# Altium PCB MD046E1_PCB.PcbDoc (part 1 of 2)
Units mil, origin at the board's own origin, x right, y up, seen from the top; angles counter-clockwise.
Board outline 4143.7 x 2795.28 mil, 4 copper layers (Top Layer, Signal Layer 1, Signal Layer 2, Bottom Layer), stack 62.8 mil thick; 159 components, 76 nets, 432 pads, 579 vias.
Unrouted connection lines stored in the file: 13.
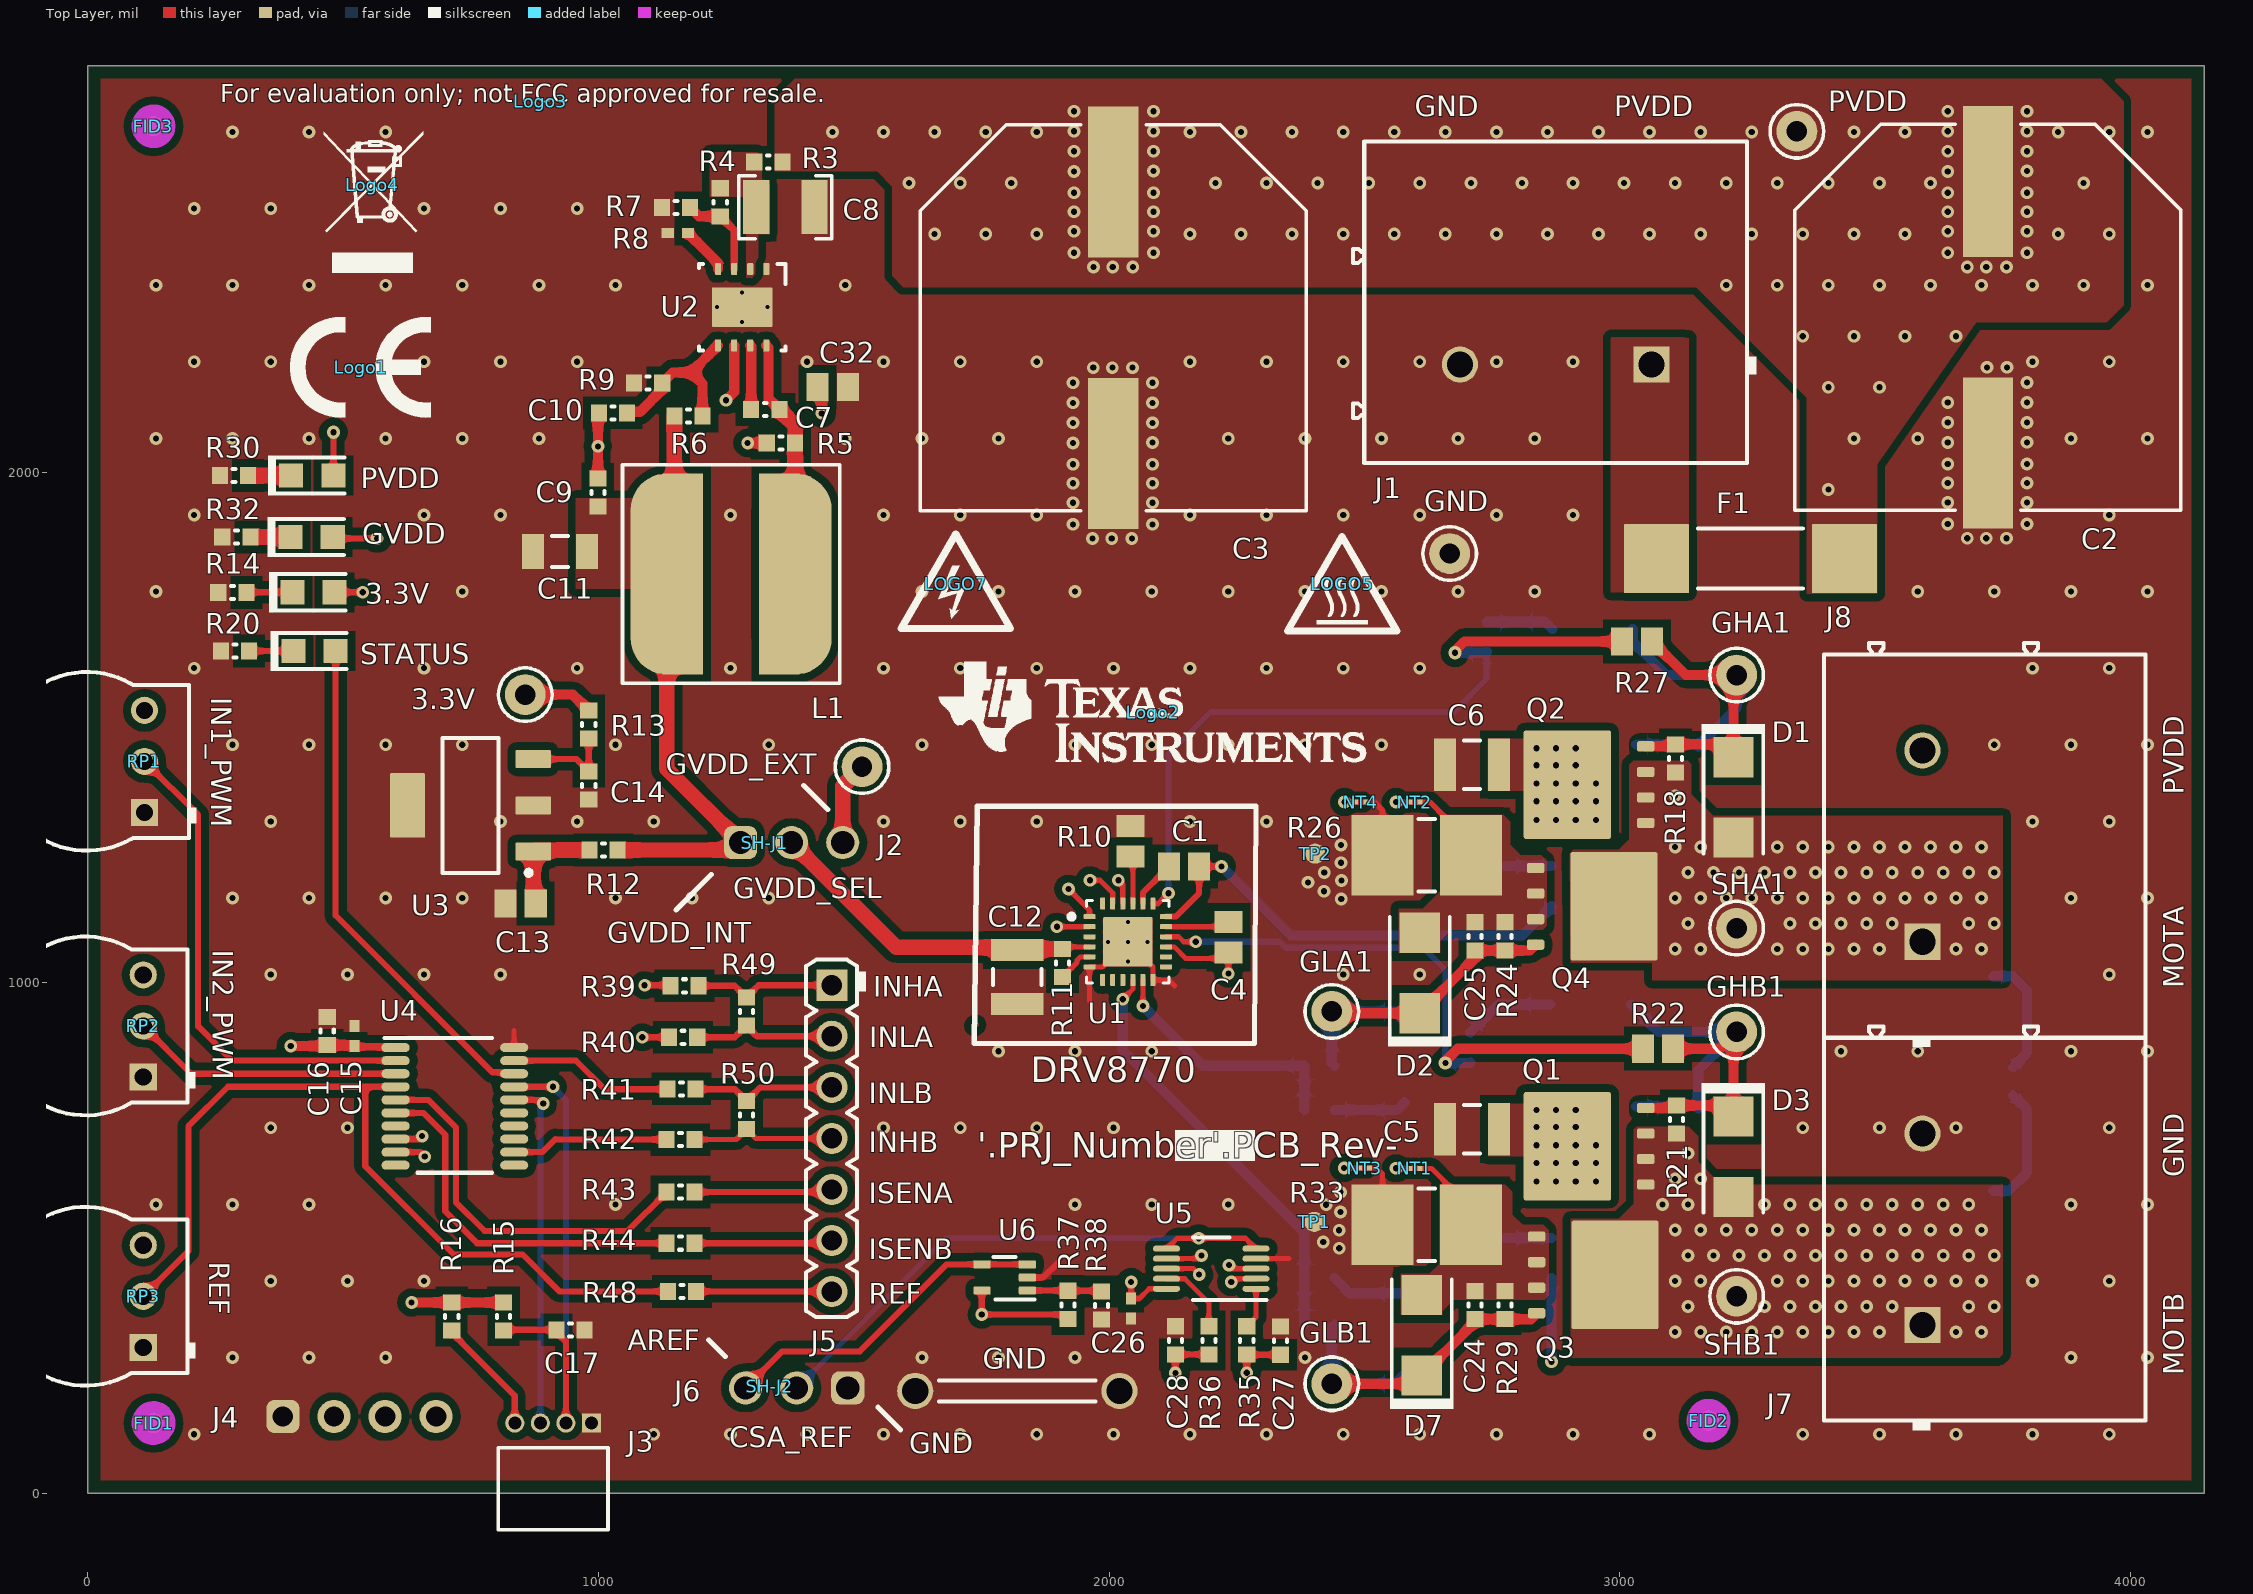
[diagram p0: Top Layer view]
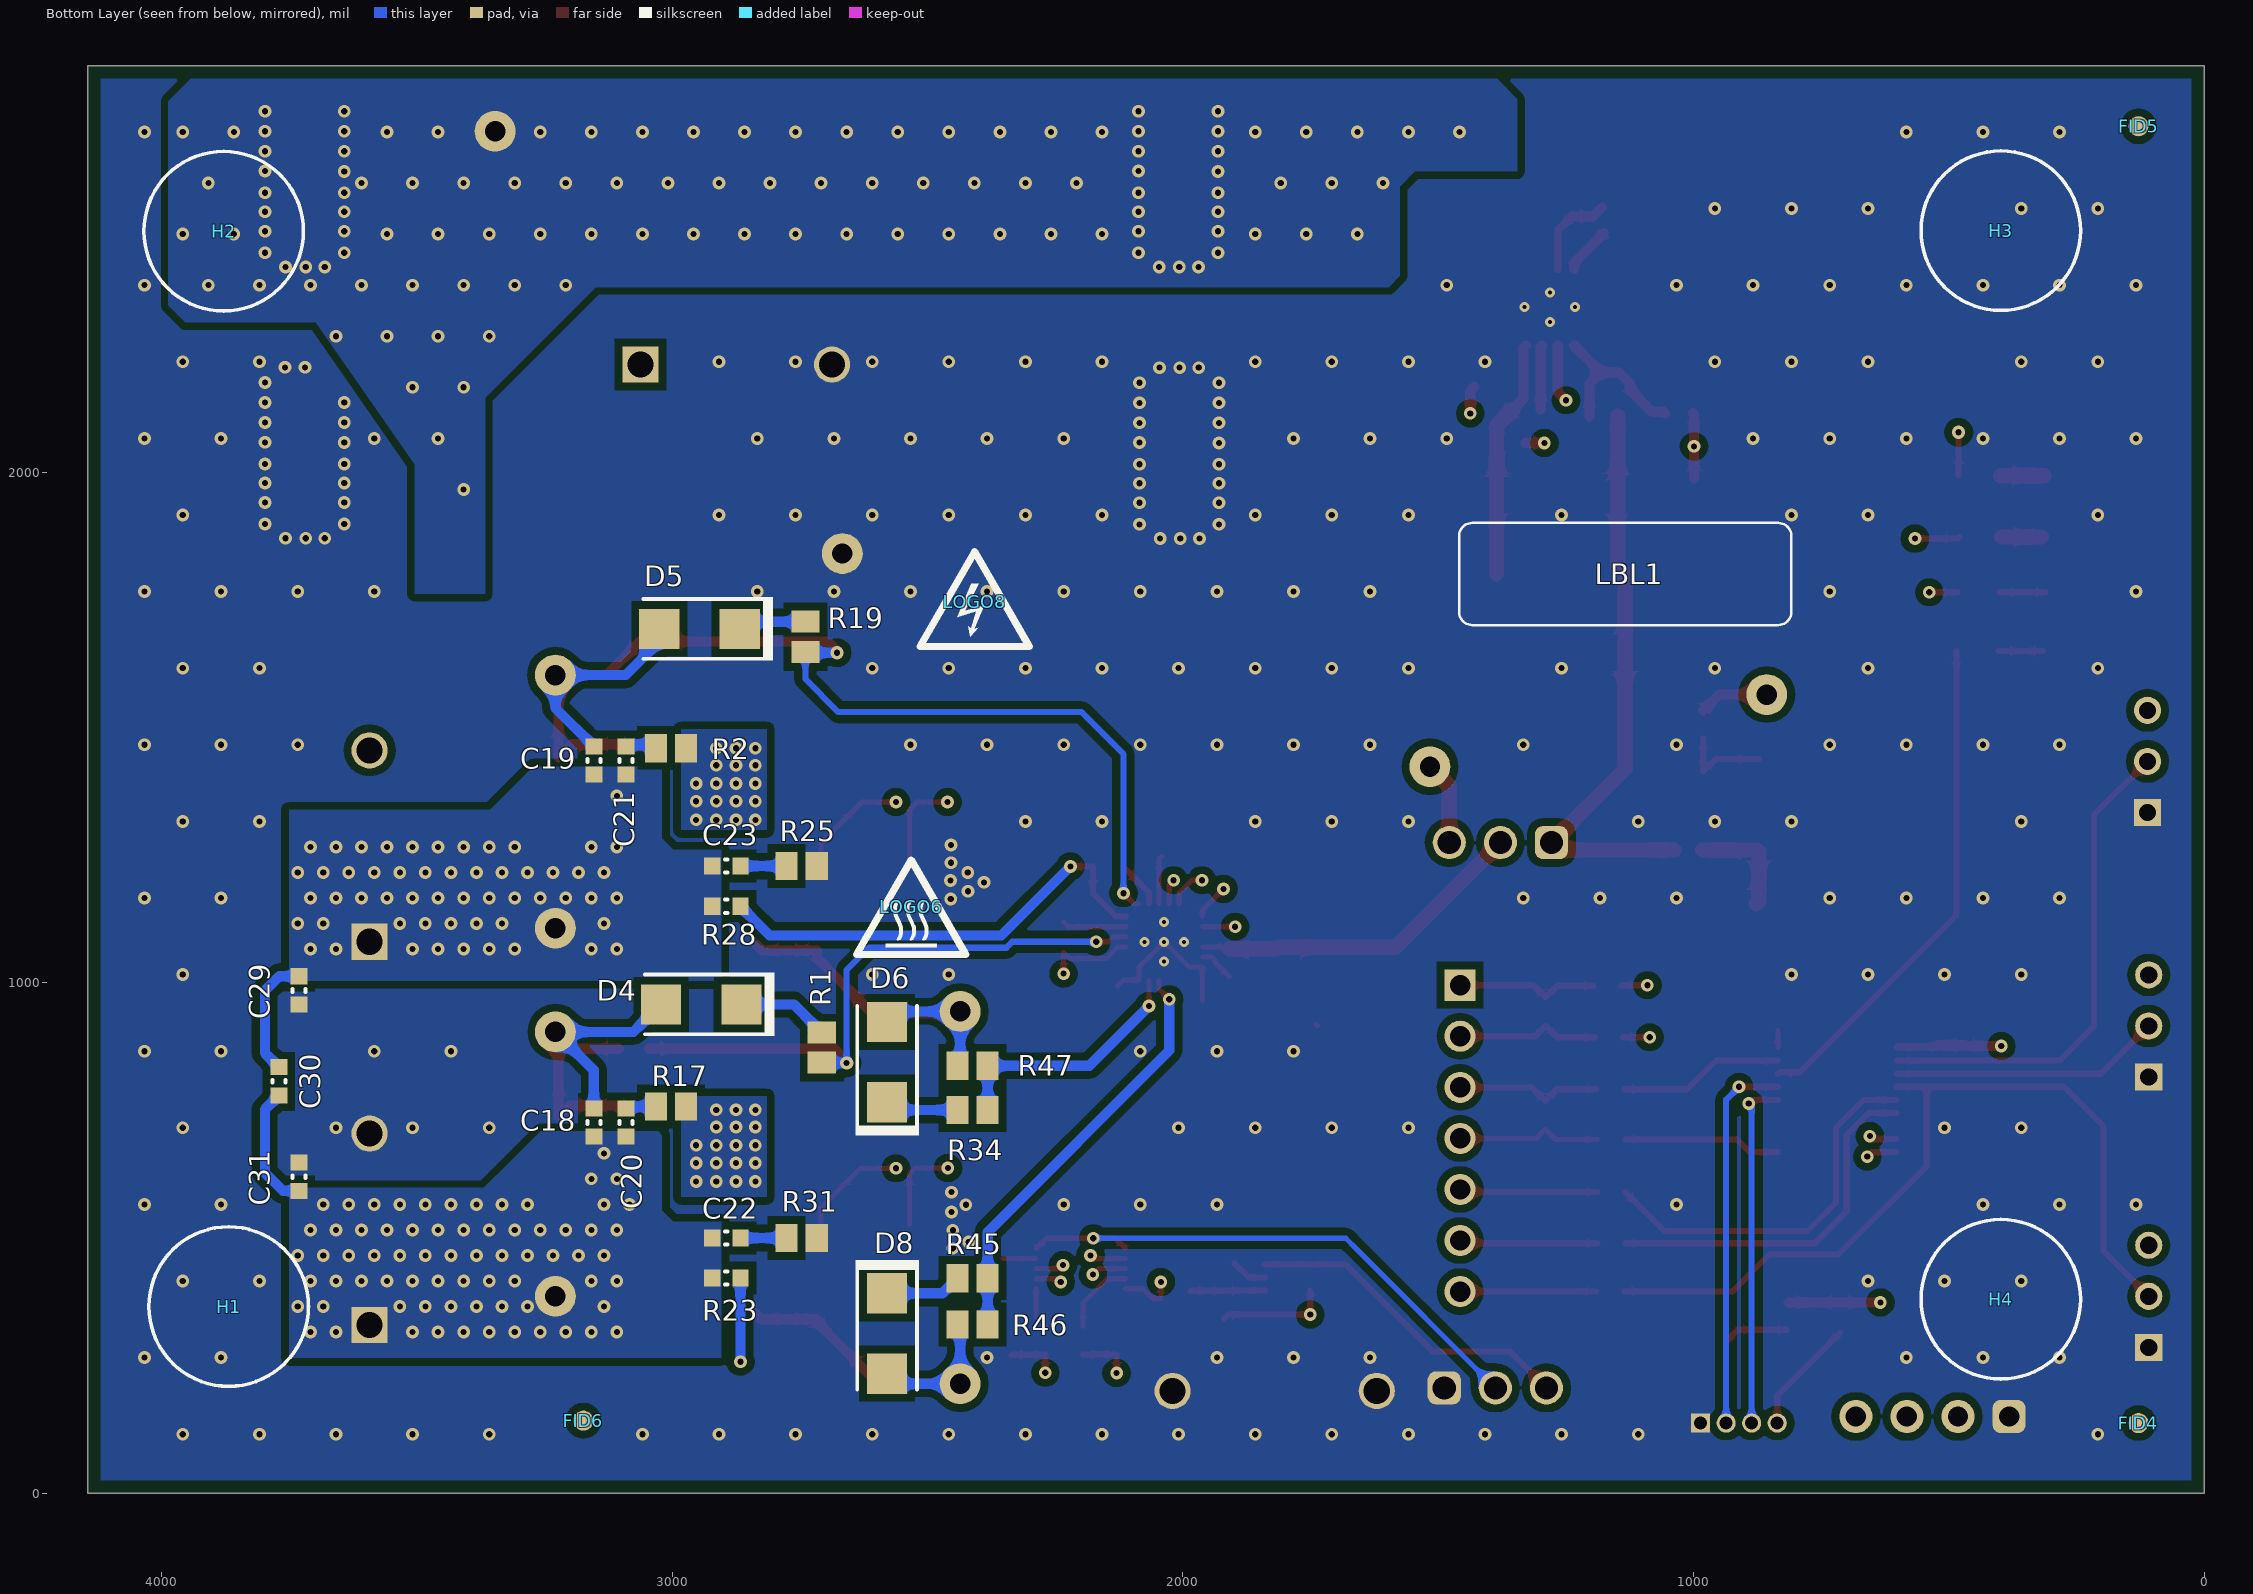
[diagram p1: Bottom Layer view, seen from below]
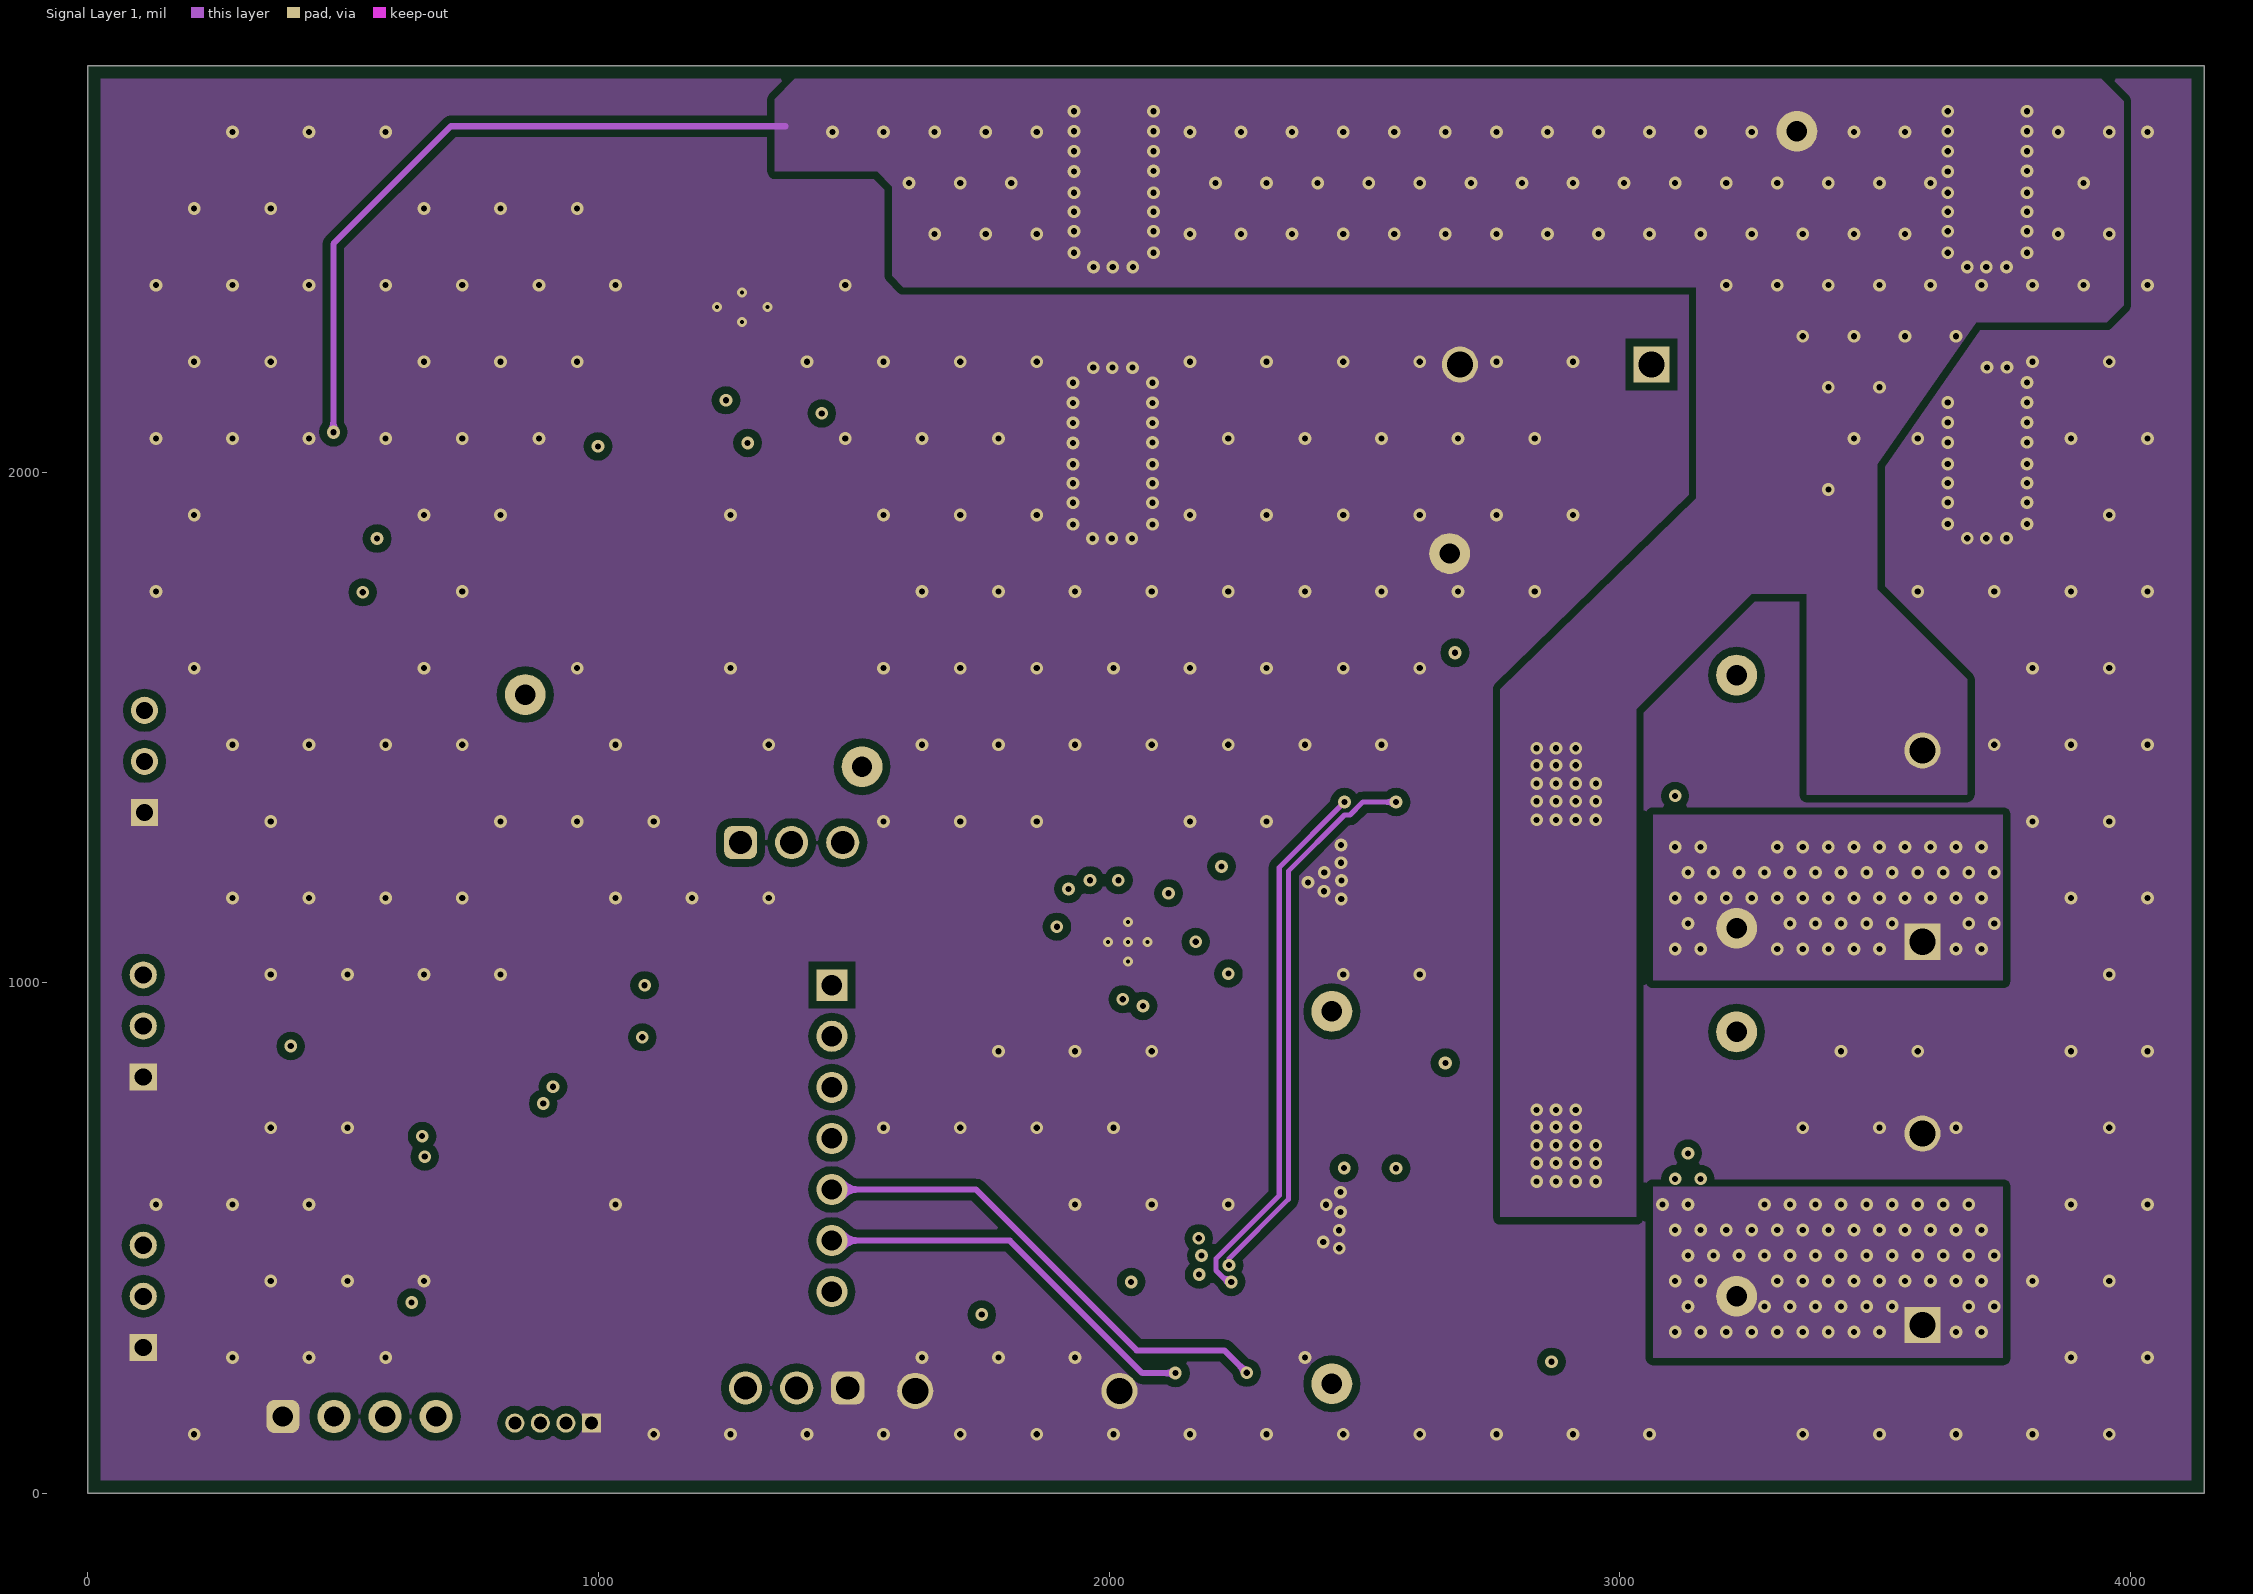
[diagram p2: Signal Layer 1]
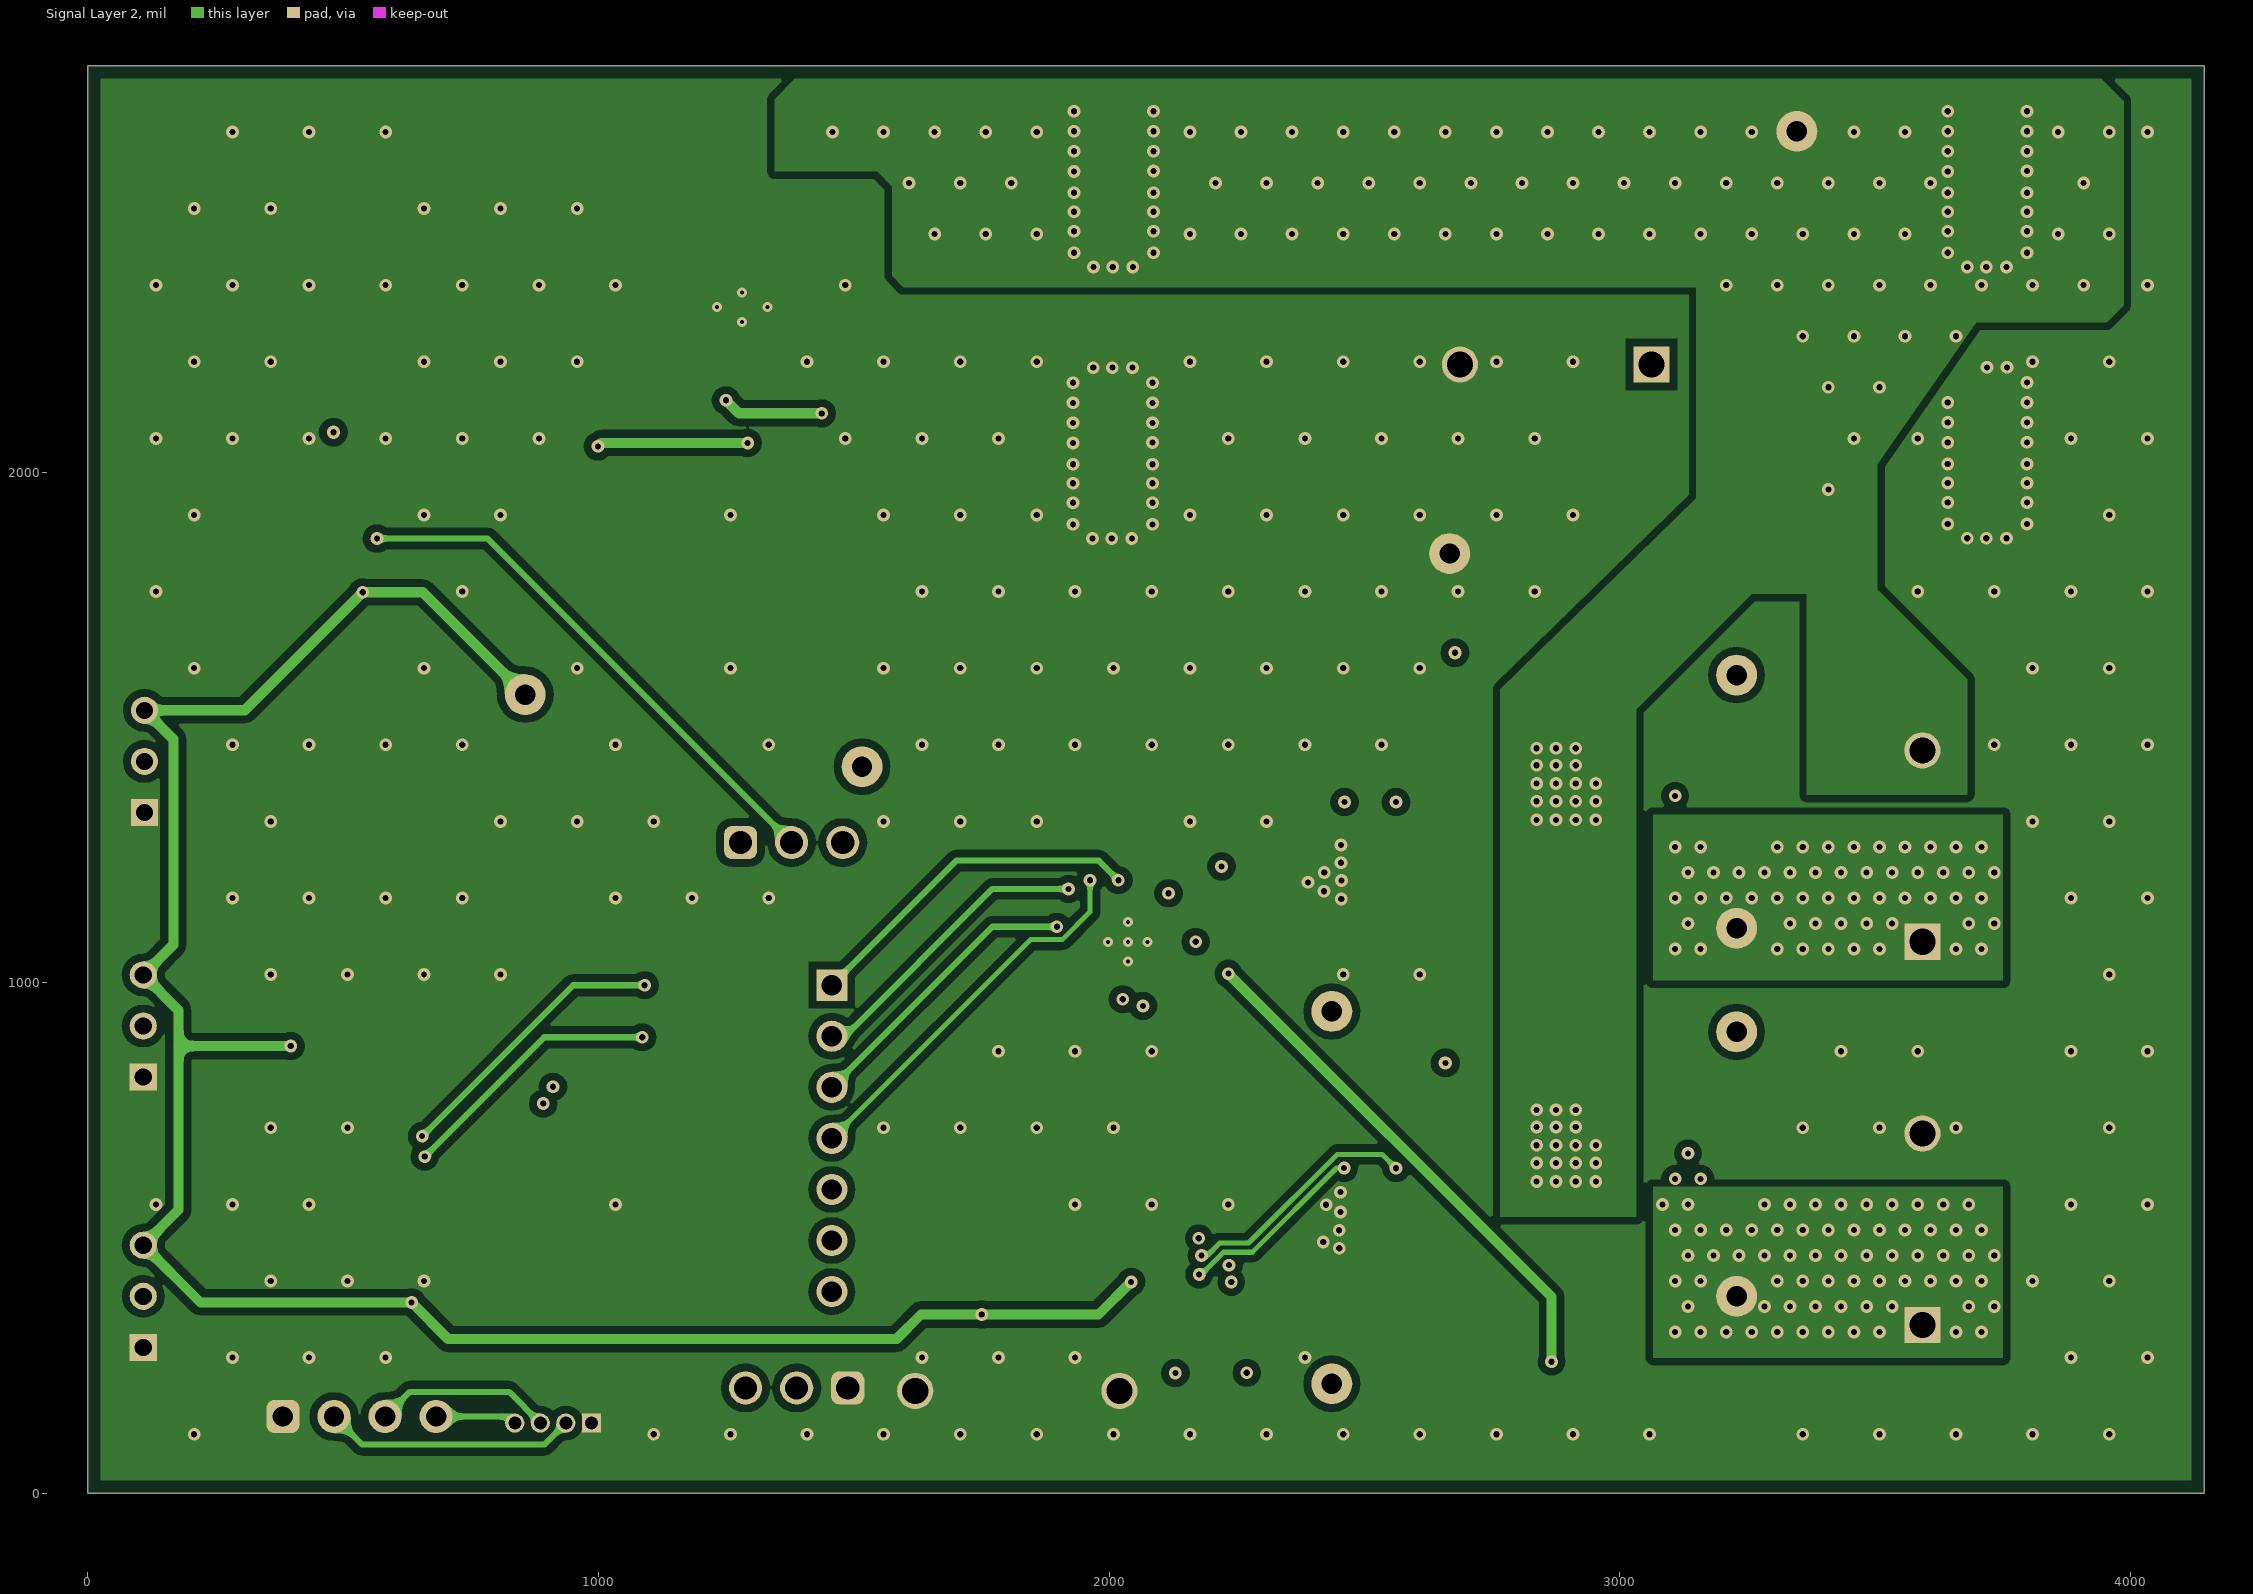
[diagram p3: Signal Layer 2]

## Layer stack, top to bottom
Top Solder: solder mask 0.4, Solder Resist, Dk 3.5
Top Layer: signal copper 2.8
Dielectric 1: prepreg 8, FR-4, Dk 4.2
Signal Layer 1: signal copper 1.4
Dielectric 2: core 38.4, FR-4, Dk 4.2
Signal Layer 2: signal copper 1.4
Dielectric 3: prepreg 8, FR-4, Dk 4.2
Bottom Layer: signal copper 2.8
Bottom Solder: solder mask 0.4, Solder Resist, Dk 3.5

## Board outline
0,0 4143.7,0 4143.7,2795.28 0,2795.28
cut-out: -692,-1534 -682,-1534 -682,-1524 -692,-1524

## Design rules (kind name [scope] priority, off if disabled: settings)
AcuteAngle [All] p1: minimum=4.50000000000000E+0001 checktracksonly=FALSE
AssemblyTestPointUsage [All] p1: valid=2
BoardOutlineClearance BoardOutlineClearance_MountingHoles [OnCopper and InComponentClass('Mounting Holes')] p1: gap=39.37 ignorepadtopadclearanceinfootprint=FALSE
BoardOutlineClearance BoardOutlineClearance_Poly [OnCopper and IsPoly] p2: gap=25 ignorepadtopadclearanceinfootprint=FALSE
BoardOutlineClearance [OnCopper and Not InComponentClass('Logo') and not InComponentClass('FiducialMark') and not InRegion(1000,500,4000,800) and not InPoly] p3: gap=75 ignorepadtopadclearanceinfootprint=FALSE
Clearance Clearance_Keepouts [((IsTrack Or IsArc) And Not InPoly) And IsFree and IsKeepOut vs ((IsTrack Or IsArc) And Not InPoly) And IsFree and IsKeepOut] p1: gap=0 ignorepadtopadclearanceinfootprint=FALSE
Clearance Clearance_Poly [InPolygon] p2: gap=15 ignorepadtopadclearanceinfootprint=TRUE
Clearance Clearance_FiducialMark [IsKeepOut and InComponentClass('FiducialMark') vs IsPad and InComponentClass('FiducialMark')] p3: gap=0 ignorepadtopadclearanceinfootprint=FALSE
Clearance [All] p4: gap=7.87 ignorepadtopadclearanceinfootprint=TRUE
ComponentClearance ComponentClearance_MountingHoles_FiducialMarks [InComponentClass('Mounting Holes') vs InComponentClass('FiducialMark')] p1: gap=50 collisioncheckmode=3 verticalgap=10 showdistances=FALSE
ComponentClearance ComponentClearance_Shunt [InComponentClass('Header') vs InComponentClass('Shunt')] p2: gap=0 collisioncheckmode=3 verticalgap=0 showdistances=FALSE
ComponentClearance ComponentClearance_Logo [InComponentClass('Logo')] p3: gap=50 collisioncheckmode=3 verticalgap=10 showdistances=FALSE
ComponentClearance ComponentClearance_ScrewToNut [(HasFootprint('NY PMS 440 0025 PH')) vs (HasFootprint('Keystone_1902C'))] p4: gap=5 collisioncheckmode=3 verticalgap=10 showdistances=FALSE
ComponentClearance ComponentClearance_MountingHoles [InComponentClass('Mounting Holes')] p5: gap=250 collisioncheckmode=3 verticalgap=100000 showdistances=FALSE
ComponentClearance ComponentClearance_SmallPassives [HasFootprint('0201*') or HasFootprint('0402*') or HasFootprint('0508') or HasFootprint('0603*') or HasFootprint('0612') or HasFootprint('0805*') or HasFootprint('0815*') or HasFootprint('0830*') or HasFootprint('1206*') or HasFootprint('1210*') or HasFootprint('1808*') or HasFootprint('1812*') or HasFootprint('1825*') or HasFootprint('2010*') or HasFootprint('2220*') or HasFootprint('2225*') or HasFootprint('2512*') or HasFootprint('2728*') or HasFootprint('3518*') vs HasFootprint('0201*') or HasFootprint('0402*') or HasFootprint('0508') or HasFootprint('0603*') or HasFootprint('0612') or HasFootprint('0805*') or HasFootprint('0815*') or HasFootprint('0830*') or HasFootprint('1206*') or HasFootprint('1210*') or HasFootprint('1808*') or HasFootprint('1812*') or HasFootprint('1825*') or HasFootprint('2010*') or HasFootprint('2220*') or HasFootprint('2225*') or HasFootprint('2512*') or HasFootprint('2728*') or HasFootprint('3518*')] p6: gap=14.96 collisioncheckmode=3 verticalgap=10 showdistances=FALSE
ComponentClearance ComponentClearance_THtoSMT [IsThruComponent vs IsSMTComponent] p7: gap=40 collisioncheckmode=3 verticalgap=30 showdistances=FALSE
ComponentClearance ComponentClearance_THtoTH [IsThruComponent vs IsThruComponent] p8: gap=30 collisioncheckmode=3 verticalgap=30 showdistances=FALSE
ComponentClearance [All] p9: gap=30 collisioncheckmode=3 verticalgap=10 showdistances=FALSE
DiffPairsRouting [All] p1: maxlimit=100 minlimit=10 mostfreqgap=10 toplayer_minwidth=15 toplayer_maxwidth=15 toplayer_prefwidth=15 midlayer1_minwidth=15 midlayer1_maxwidth=15 midlayer1_prefwidth=15 midlayer2_minwidth=15 midlayer2_maxwidth=15 midlayer2_prefwidth=15 bottomlayer_minwidth=15 bottomlayer_maxwidth=15 bottomlayer_prefwidth=15 maxuncoupledlength=1000
FabricationTestPointUsage TestPointUsage [All] p1: valid=2 allowmultiple=FALSE
FabricationTestpoint Testpoint [All] p1: side=3 testpointundercomponent=TRUE minsize=40 maxsize=100 preferedsize=60 minholesize=0 maxholesize=40 preferedholesize=32 testpointgrid=1 allowsidetop=TRUE allowsidebottom=TRUE usegrid=TRUE gridtolerance=0.01
FanoutControl Fanout_LCC [IsLCC] p1: bgadir=Out bgaviamode=Centered fanoutstyle=Auto fanoutdirection=Alternating viagrid=1 // Fanout_LCC (Default Rule)
FanoutControl Fanout_BGA [IsBGA] p2: bgadir=Out bgaviamode=Centered fanoutstyle=Auto fanoutdirection=Alternating viagrid=1 // Fanout_BGA (Default Rule)
FanoutControl Fanout_Default [All] p4: bgadir=Out bgaviamode=Centered fanoutstyle=Auto fanoutdirection=Alternating viagrid=1 // Fanout_Default (Default Rule)
FanoutControl Fanout_Small [(CompPinCount < 5)] p5: bgadir=Out bgaviamode=Centered fanoutstyle=Auto fanoutdirection=OutThenIn viagrid=1 // Fanout_Small (Default Rule)
HoleSize [All] p1: absolutevalues=TRUE maxlimit=251 minlimit=7.87 maxpercent=80.000 minpercent=20.000
MinimumAnnularRing MinimumAnnularRing_ThermalPadVias [IsVia and InAnyComponent] p1: minimumring=5.91
MinimumAnnularRing [All] p2: minimumring=7.87
MinimumSolderMaskSliver MinimumSolderMaskSliver_Logo [InComponentClass('Logo') vs InComponentClass('Logo')] p1: minsoldermaskwidth=0.7
MinimumSolderMaskSliver [All] p2: minsoldermaskwidth=3.94
PlaneConnect [All] p1: planeconnectstyle=Direct reliefexpansion=10 reliefentries=4 reliefconductorwidth=10 reliefairgap=10
PolygonConnect PolygonConnect_4 [All vs IsNamedPolygon('TOP_LAYER_NETC8_1_P000')] p1: connectstyle=Direct reliefconductorwidth=10 reliefentries=4 polygonreliefangle="90 Angle" airgapwidth=10
PolygonConnect PolygonConnect_3 [All vs IsNamedPolygon('TOP_LAYER_PVDD_P008')] p2: connectstyle=Direct reliefconductorwidth=10 reliefentries=4 polygonreliefangle="90 Angle" airgapwidth=10
PolygonConnect PolygonConnect_2 [All vs IsNamedPolygon('TOP_LAYER_PVDD_P014')] p3: connectstyle=Direct reliefconductorwidth=10 reliefentries=4 polygonreliefangle="90 Angle" airgapwidth=10
PolygonConnect PolygonConnect_1 [All vs IsNamedPolygon('TOP_LAYER_NETF1_2_P010')] p4: connectstyle=Direct reliefconductorwidth=10 reliefentries=4 polygonreliefangle="90 Angle" airgapwidth=10
PolygonConnect [All] p5: connectstyle=Direct reliefconductorwidth=10 reliefentries=4 polygonreliefangle="90 Angle" airgapwidth=10
RoutingVias ThermalPadVias [IsVia and InAnyComponent] p1: holewidth=7.87 width=19.68 viastyle="Through Hole" minholewidth=7.87 minwidth=19.68 maxholewidth=12.99 maxwidth=23.62
RoutingVias [All] p2: holewidth=16 width=34 viastyle="Through Hole" minholewidth=7.87 minwidth=26 maxholewidth=40 maxwidth=65
SilkToBoardRegionClearance [Not ((IsComment or IsDesignator) And (Hide <> 'False')) and not InRegion(1000,500,4000,800)] p1:
SilkToSilkClearance SilkToSilkClearance_Pb-FreeLogo [(HasFootprint('Pb-Free_Overlay_Medium') OR HasFootprint('Pb-Free_Overlay_Small')) vs (HasFootprint('Pb-Free_Overlay_Medium') OR HasFootprint('Pb-Free_Overlay_Small'))] p1: silktosilkclearance=0
SilkToSilkClearance [All] p2: silktosilkclearance=3.94
SilkToSolderMaskClearance SilkToComponentPadClearance [(IsPad or IsFill or IsRegion) and InAnycomponent] p1: minsilkscreentomaskgap=5 clearancetoexposedcopper=TRUE
SilkToSolderMaskClearance "Silk to Solder Mask Opening" [All] p2: minsilkscreentomaskgap=3.94 clearancetoexposedcopper=FALSE
SolderMaskExpansion [All] p1: expansion=1.97
UnRoutedNet [All] p1: checkbadconnections=TRUE
Width [All] p1: maxlimit=100 minlimit=6 preferedwidth=10 checkconnectedcopper=TRUE
14 further rules are at their usual default settings.

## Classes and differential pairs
component class MD046E1_SCH: 3.3V C1 C2 C3 C4 C5 C6 C7 C8 C9 C10 C11 C12 C13 C14 C15 C16 C17 C18 C19 C20 C21 C22 C23 C24 C25 C26 C27 C28 C29 C30 C31 C32 D1 D2 D3 D4 D5 D6 D7 D8 F1 GHA1 GHB1 GLA1 GLB1 GND GVDD GVDD_EXT J1 J2 J3 J4 J5 J6 J7 J8 L1 NT1 NT2 NT3 NT4 PVDD Q1 Q2 Q3 Q4 R1 R2 R3 R4 R5 R6 R7 R8 R9 R10 R11 R12 R13 R14 R15 R16 R17 R18 R19 R20 R21 R22 R23 R24 R25 R26 R27 R28 R29 R30 R31 R32 R33 R34 R35 R36 R37 R38 R39 R40 R41 R42 R43 R44 R45 R46 R47 R48 R49 R50 RP1 RP2 RP3 SH-J1 SH-J2 SHA1 SHB1 STATUS TP1 TP2 U1 U2 U3 U4 U5 U6
component class MD046E1_Hardware: FID1 FID2 FID3 FID4 FID5 FID6 H1 H2 H3 H4 LBL1 Logo1 Logo2 Logo3 Logo4 LOGO5 LOGO6 LOGO7 LOGO8 ZZ1 ZZ2 ZZ3 ZZ4

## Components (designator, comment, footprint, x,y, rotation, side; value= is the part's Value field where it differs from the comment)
3.3V "" Keystone5000 856.3,1564.22 r90 top
3.3V "" LED_LTST-C171 441.55,1764.59 r180 top value=Green
C1 "CL21B105KAFNNNE" 0805L 2146.46,1227.86 r0 top value=1uF
C2 "EEV-FK2A331M" SM_RADIAL_K16 3720.47,2303.15 r270 top value=330uF
C3 "EEV-FK2A331M" SM_RADIAL_K16 2007.87,2302.41 r270 top value=330uF
C4 "CL21B105KAFNNNE" 0805L 2233.07,1089.08 r270 top value=1uF
C5 "CGA6M2X7R2A105K200AA" 1210_220L 2710.24,713.34 r180 top value=1uF
C6 "CGA6M2X7R2A105K200AA" 1210_220L 2710.24,1427.07 r180 top value=1uF
C7 "C0603C103J1RACTU" 0603L 1326.32,2122.29 r0 top value=0.01uF
C8 "CGA6M2X7R2A105K200AA" 1210_220 1365.69,2518.94 r0 top value=1uF
C9 "CGA3E2X7R2A222K080AA" 0603L 998.57,1959.89 r90 top value=2200pF
C10 "GRM1885C2A560JA01D" 0603L 1028.09,2115.4 r0 top value=56pF
C11 "C3216X5R1E476M160AC" 1206_190L 924.38,1844.33 r180 top value=47uF
C12 "CL32B106KBJNNWE" 1210_270L 1819.69,1011.33 r270 top value=10uF
C13 "08053D334KAT2A" 0805L 847.23,1155.03 r180 top value=0.33uF
C14 "C0603C104J4RACTU" 0603L 980.64,1386.49 r270 top value=0.1uF
C15 "C1005X5R1A475K050BC" 0402_065L 521.65,895.67 r90 top value=4.7uF
C16 "C0603C104K8RACTU" 0603L 468.5,905.51 r90 top value=0.1uF
C17 "C0603C102J5RACAUTO" 0603L 944.88,320.42 r0 top value=1000pF
C18 "06031C222KAT2A" 0603L 3153.15,726.59 r270 bottom value=2200pF
C19 "06031C222KAT2A" 0603L 3153.15,1435.25 r270 bottom value=2200pF
C20 "GRM188R72A222KA01D" 0603L 3090.16,726.59 r270 bottom value=2200pF
C21 "GRM188R72A222KA01D" 0603L 3090.16,1435.25 r270 bottom value=2200pF
C22 "GRM188R72A222KA01D" 0603L 2893.7,500.21 r180 bottom value=2200pF
C23 "GRM188R72A222KA01D" 0603L 2893.7,1228.56 r180 bottom value=2200pF
C24 "06031C222KAT2A" 0603L 2716.14,368.85 r90 top value=2200pF
C25 "06031C222KAT2A" 0603L 2716.14,1090.89 r90 top value=2200pF
C26 "C0402C104K8RACAUTO" 0402L 2042.81,361.97 r270 top value=0.1uF
C27 "885012206081" 0603L 2334.87,299.07 r90 top value=470pF
C28 "885012206081" 0603L 2129.3,299.85 r90 top value=470pF
C29 "06031C102JAT2A" 0603L 3730.31,985.16 r90 bottom value=1000pF
C30 "06031C102JAT2A" 0603L 3769.69,807.09 r270 bottom value=1000pF
C31 "06031C102JAT2A" 0603L 3730.31,620.08 r90 bottom value=1000pF
C32 "CL21B105KAFNNNE" 0805L 1458.48,2166.88 r0 top value=1uF
D1 "SMAZ16-13-F" SMA 3222.05,1362.94 r270 top value=16V
D2 "SMAZ16-13-F" SMA 2608,1019.01 r90 top value=16V
D3 "SMAZ16-13-F" SMA 3222.05,659.45 r270 top value=16V
D4 "SSA24-E3/61T" SMA 2942.91,957.6 r0 bottom value=40V
D5 "SSA24-E3/61T" SMA 2946.13,1692.91 r0 bottom value=40V
D6 "SSA24-E3/61T" SMA 2578.74,844.7 r90 bottom value=40V
D7 "SMAZ16-13-F" SMA 2611.81,309.79 r90 top value=16V
D8 "SSA24-E3/61T" SMA 2578.74,313.2 r270 bottom value=40V
F1 "100VDC 30A" Fuse_0463 3255.51,1830.71 r180 top
FID1 "Fiducial" Fiducial10-20#1 128.36,137.81 r0 top
FID2 "Fiducial" Fiducial10-20#1 3173.51,142.51 r0 top
FID3 "Fiducial" Fiducial10-20#1 128.32,2677.17 r0 top
FID4 "Fiducial" Fiducial10-20#2 128.36,137.81 r0 top
FID5 "Fiducial" Fiducial10-20#2 128.32,2677.17 r0 top
FID6 "Fiducial" Fiducial10-20#2 3173.51,142.51 r0 top
GHA1 "5002" Keystone5002 3228.35,1602.57 r90 top
GHB1 "5002" Keystone5002 3228.35,903.75 r90 top
GLA1 "5002" Keystone5002 2435.74,943.82 r90 top
GLB1 "5002" Keystone5002 2435.74,214.78 r90 top
GND "5001" Keystone5001 2666.5,1840.55 r90 top
GND "D3082-05" Harwin_D3082-05 1819.89,200.79 r180 top
GVDD "" LED_LTST-C171 437.91,1872.86 r180 top value=Green
GVDD_EXT "" Keystone5000 1515.75,1423.09 r90 top
H1 "SJ61A1" Bumpon_SJ61A1 3868.11,366 r180 bottom
H2 "SJ61A1" Bumpon_SJ61A1 3877.95,2471.7 r180 bottom
H3 "SJ61A1" Bumpon_SJ61A1 397.94,2472.88 r180 bottom
H4 "SJ61A1" Bumpon_SJ61A1 397.94,380.32 r180 bottom
J1 "PVDD INPUT" Phoenix_1902547 2874.02,2332.68 r180 top
J2 "GVDD_PWR_SEL" WURTH_61300311121 1377.95,1274.44 r0 top
J3 "851-43-004-20-001000" CONN_851-43-004-20-001000 910.83,137.8 r0 top
J4 "TSW-104-07-G-S" TSW-104-07-G-S 531.75,150.63 r0 top
J5 "PBC07SFAN" Sullins_xxC07SFAN 1456.69,695.23 r270 top
J6 "GVDD_PWR_SEL" WURTH_61300311121 1387.8,206.69 r180 top
J7 "" Phoenix_1902547 3714.17,517.32 r90 top
J8 "" Phoenix_1902547 3714.17,1267.63 r90 top
L1 "SDR1006-680KL" SDR1006 1259.39,1800.44 r180 top value=68uH
LBL1 "THT-14-423-10" Label_650x200 1133.41,1800.44 r180 bottom
Logo1 "CE Mark" CE_Mark_5mm 533.79,2205.07 r0 top
Logo2 "Texas Instruments" TI_Stacked_Overlay_Small 2084.64,1529.97 r0 top
Logo3 "FCC disclaimer" FCC_disclaimer 885.83,2726.38 r0 top
Logo4 "WEEE logo" WEEE_Minimum 556.89,2562.77 r0 top
LOGO5 "CAUTION HOT SURFACE" IEC_HotSurface_Small 2455.77,1781.5 r0 top
LOGO6 "CAUTION HOT SURFACE" IEC_HotSurface_Small 2531.69,1148.38 r180 bottom
LOGO7 "DANGER HIGH VOLTAGE" IEC_HighVoltage_Small 1699.34,1781.5 r0 top
LOGO8 "DANGER HIGH VOLTAGE" IEC_HighVoltage_Small 2407.44,1746.57 r180 bottom
NT1 "Net-Tie" Net-Tie_10mil 2598.43,636.66 r0 top net-tie
NT2 "Net-Tie" Net-Tie_10mil 2598.43,1353.74 r0 top net-tie
NT3 "Net-Tie" Net-Tie_10mil 2499.84,637.15 r0 top net-tie
NT4 "Net-Tie" Net-Tie_10mil 2492.48,1353.74 r0 top net-tie
PVDD "5000" Keystone5000 3346.46,2667.32 r90 top
PVDD "" LED_LTST-C171 439.28,1993.09 r180 top value=Green
Q1 "CSD19532Q5B" DNK0008A 2939.37,679.72 r180 top value=100V
Q2 "CSD19532Q5B" DNK0008A 2939.37,1387.94 r180 top value=100V
Q3 "CSD19532Q5B" DNK0008A 2947.83,427.9 r0 top value=100V
Q4 "CSD19532Q5B" DNK0008A 2945.87,1149.56 r0 top value=100V
R1 "ERJ-6GEYJ100V" 0805L 2706.69,873.03 r90 bottom value=10
R2 "CRCW08052R70JNEA" 0805L 3001.97,1459.33 r180 bottom value=2.7
R3 "CRCW06030000Z0EA" 0603L 1332.23,2607.53 r180 top value=0
R4 "CRCW06031M00JNEA" 0603L 1238.13,2528.32 r90 top value=1.0Meg
R5 "RC0603FR-07681KL" 0603L 1356.83,2057.09 r180 top value=681k
R6 "RC0603FR-07453KL" 0603L 1175.73,2109.49 r180 top value=453k
R7 "CRCW0603330KJNEA" 0603L 1151.57,2518.14 r0 top value=330k
R8 "CRCW0402100KFKED" 0402L 1155.06,2468.34 r0 top value=100k
R9 "RC0603FR-0749K9L" 0603L 1096.99,2174.46 r0 top value=49.9k
R10 "CRCW08050000Z0EAHP" 0805L 2041.74,1277.08 r270 top value=0
R11 "CRCW06030000Z0EA" 0603L 1908.27,1038.89 r90 top value=0
R12 "CRCW06030000Z0EA" 0603L 1009.39,1259.84 r180 top value=0
R13 "CRCW06030000Z0EA" 0603L 980.64,1505.58 r90 top value=0
R14 "CRCW0603330RJNEA" 0603L 282.77,1764.59 r0 top value=330
R15 "CRCW060347K0JNEA" 0603L 813.88,346.46 r90 top value=47k
R16 "CRCW06030000Z0EA" 0603L 712.4,346.46 r90 top value=0
R17 "CRCW08052R70JNEA" 0805L 3001.97,757.87 r180 bottom value=2.7
R18 "CRCW0603100KFKEA" 0603L 3108.86,1439.32 r270 top value=100k
R19 "ERJ-6GEYJ100V" 0805L 2738.94,1677.57 r90 bottom value=10
R20 "CRCW0603330RJNEA" 0603L 287.76,1649.68 r0 top value=330
R21 "CRCW0603100KFKEA" 0603L 3110.83,732.08 r270 top value=100k
R22 "ERJ-6GEYJ150V" 0805L 3074.41,870.82 r0 top value=15
R23 "RCS06030000Z0EA" 0603L 2893.7,421.47 r0 bottom value=0
R24 "CRCW0603100KFKEA" 0603L 2775.2,1090.89 r90 top value=100k
R25 "CRCW08052R70JNEA" 0805L 2746.06,1228.56 r0 bottom value=2.7
R26 "LRMAP2512-R002FT4" LRMA2512_under3 2621.65,1249.36 r0 top value=0.002
R27 "ERJ-6GEYJ150V" 0805L 3033.49,1668.26 r0 top value=15
R28 "RCS06030000Z0EA" 0603L 2893.7,1149.82 r0 bottom value=0
R29 "CRCW0603100KFKEA" 0603L 2775.2,368.85 r90 top value=100k
R30 "CRCW06034K99FKEA" 0603L 286.1,1993.09 r0 top value=4.99k
R31 "CRCW08052R70JNEA" 0805L 2746.06,500.21 r0 bottom value=2.7
R32 "CRCW06034K99FKEA" 0603L 290.56,1872.86 r0 top value=4.99k
R33 "LRMAP2512-R002FT4" LRMA2512_under3 2621.65,526.33 r0 top value=0.002
R34 "ERJ-6GEYJ100V" 0805L 2411.42,750.78 r0 bottom value=10
R35 "RCS06030000Z0EA" 0603L 2269.1,299.85 r270 top value=0
R36 "RCS06030000Z0EA" 0603L 2194.88,299.85 r270 top value=0
R37 "CRCW0603100KFKEA" 0603L 1919.29,369.27 r270 top value=100k
R38 "CRCW0603100KFKEA" 0603L 1984.45,368.13 r90 top value=100k
R39 "RCS06030000Z0EA" 0603L 1167.89,994.09 r0 top value=0
R40 "RCS06030000Z0EA" 0603L 1165.57,893.23 r0 top value=0
R41 "RCS06030000Z0EA" 0603L 1162.49,791.57 r0 top value=0
R42 "RCS06030000Z0EA" 0603L 1160.52,693.14 r0 top value=0
R43 "RCS06030000Z0EA" 0603L 1160.52,589.99 r0 top value=0
R44 "RCS06030000Z0EA" 0603L 1160.52,489.99 r0 top value=0
R45 "ERJ-6GEYJ100V" 0805L 2411.42,421.47 r0 bottom value=10
R46 "ERJ-6GEYJ150V" 0805L 2411.42,330.82 r0 bottom value=15
R47 "ERJ-6GEYJ150V" 0805L 2411.42,837.35 r0 bottom value=15
R48 "RCS06030000Z0EA" 0603L 1163.32,395.71 r0 top value=0
R49 "RCS06030000Z0EA" 0603L 1289.37,943.65 r90 top value=0
R50 "RCS06030000Z0EA" 0603L 1289.84,741.03 r270 top value=0
RP1 "3352T-1-503LF" Bourns_3352T 110.65,1433.49 r90 top value=50k
RP2 "3352T-1-503LF" Bourns_3352T 108.27,915.35 r90 top value=50k
RP3 "3352T-1-503LF" Bourns_3352T 108.3,386.04 r90 top value=50k
SH-J1 "SNT-100-BK-G" SNT-100-BK-G 1325.7,1274.44 r0 top value=1x2
SH-J2 "SNT-100-BK-G" SNT-100-BK-G 1335.27,209.82 r0 top value=1x2
SHA1 "5002" Keystone5002 3228.35,1106.88 r90 top
SHB1 "5002" Keystone5002 3228.35,386.04 r90 top
STATUS "" LED_LTST-C171 443.75,1649.68 r180 top value=Green
TP1 "TP_SM_1MM" TP_SM_1MM 2401.57,531.71 r0 top
TP2 "TP_SM_1MM" TP_SM_1MM 2403.18,1252.94 r90 top
U1 "DRV8770RGE" RGE0024B-MFG 2036.22,1080.23 r0 top
U2 "LM5017SDX/NOPB" NGU0008B 1281.13,2322.83 r270 top
U3 "UA78M33CDCYR" DCY0004A_N 748.92,1347.27 r180 top
U4 "MSP430G2553IPW20" PW0020A_N 718.5,757.87 r0 top
U5 "INA2181A1DGS" DGS0010A_N 2199.61,440.12 r180 top
U6 "TLV9001IDCKR" DCK0005A_N 1795.08,422.94 r180 top
ZZ1 "This Assembly Note is for PCB labels only" AssemblyNoteLabel 185,3938 r0 top
ZZ2 "These assemblies are ESD sensitive, ESD precautions shall be observed." AssemblyNote 185,3829.11 r0 top
ZZ3 "These assemblies must be clean and free from flux and all contaminants. Use of no clean flux is not acceptable." AssemblyNote 185,3740.56 r0 top
ZZ4 "These assemblies must comply with workmanship standards IPC-A-610 Class 2, unless otherwise specified." AssemblyNote 185,3652 r0 top

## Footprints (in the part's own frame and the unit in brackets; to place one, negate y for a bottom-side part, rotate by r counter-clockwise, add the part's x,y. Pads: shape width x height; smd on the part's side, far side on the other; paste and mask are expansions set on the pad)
0402_065L [mm] "0402"
  rect 0.6x0.5 smd: 1(-0.5,0) 2(0.5,0)
  body extent -0.55,-0.3 0.55,0.3, height 0.65
0402L [mm] "0402 from SM-752 data"
  rect 0.6x0.5 smd: 1(-0.5,0) 2(0.5,0)
  body extent -0.55,-0.3 0.55,0.3, height 0.6
0603L [mm] "0603 from SM-752 data"
  rect 0.8x0.85 smd: 1(-0.7,0) 2(0.7,0)
  silkscreen extent -0.07,-0.33 0.07,0.33, body extent -0.87,-0.47 0.87,0.47, height 1
0805L [mm] "0805 from SM-752 data"
  rect 1.1x1.4 smd: 1(-0.75,0) 2(0.75,0)
  body extent -1.1,-0.72 1.1,0.72, height 1.45
1206_190L [mm] "1206_190"
  rect 1.1x1.75 smd: 1(-1.35,0) 2(1.35,0)
  silkscreen extent -0.4,-0.77 0.4,0.77, body extent -1.75,-0.95 1.75,0.95, height 1.9
1210_220 [mm] "1210"
  rect 1.3x2.7 smd: 1(-1.45,0) 2(1.45,0)
  silkscreen extent -2.32,-1.57 2.32,1.57, body extent -1.7,-1.35 1.7,1.35, height 2.2
1210_220L [mm] "1210"
  rect 1.1x2.6 smd: 1(-1.35,0) 2(1.35,0)
  silkscreen extent -0.4,-1.2 0.4,1.2, body extent -1.7,-1.35 1.7,1.35, height 2.2
1210_270L [mm] "1210"
  rect 1.1x2.6 smd: 1(-1.35,0) 2(1.35,0)
  silkscreen extent -0.4,-1.2 0.4,1.2, body extent -1.7,-1.35 1.7,1.35, height 2.7
AssemblyNote [mil] "Assembly Note"
AssemblyNoteLabel [mil] "Assembly Note for PCB Labels"
Bourns_3352T [mm] "TH, 3-Leads, Body 9.53x8.89mm, Pitch 2.54mm"
  rect 1.35x1.35 hole 0.85: 1(-2.54,0)
  round 1.35 hole 0.85: 2(0,0) 3(2.54,0)
  silkscreen extent -4.44,-2.6 4.44,7.31, body extent -4.44,-2.21 4.45,7.32, height 3.81
Bumpon_SJ61A1 [mil] "3M Cylindrical Bumpon black"
  round 1 on Mech4: 0(0,0)
  silkscreen extent -156,-156 156,156, body extent -156,-156 156,156, height 201
CE_Mark_5mm [mil] "Minimum text height for CE Mark"
  silkscreen extent -138,-98 138,98
CONN_851-43-004-20-001000 [mm] "MILL-MAX"
  rect 0.95x0.95 hole 0.65: 1(1.905,0)
  round 0.95 hole 0.65: 2(0.635,0) 3(-0.635,0) 4(-1.905,0)
  silkscreen extent -2.73,-5.31 2.73,-1.22, body extent -2.73,-5.31 2.73,0.23, height 2.23
DCK0005A_N [mm] "SOT353, 5-Leads, Body 2x1.3mm, Pitch 0.65mm, Lead Span 2.1mm, IPC Medium Density"
  rrect25% 0.85x0.4 smd: 1(-1.125,0.65) 2(-1.125,0) 3(-1.125,-0.65) 4(1.125,-0.65) 5(1.125,0.65)
  silkscreen extent -1.48,-1.02 0.55,1.1, body extent -1.14,-1 1.14,1, height 0.95
DCY0004A_N [mm] "SOT223/SC73, 4-Leads, Body 6.5x3.5mm, Pitch 2.3mm, Lead Span 7mm, IPC Medium Density"
  rrect11% 1.75x0.9 smd: 1(-3.125,2.3) 2(-3.125,0) 3(-3.125,-2.3)
  rrect6% 1.75x3.2 smd: 4(3.125,0)
  silkscreen extent -3.03,-3.35 1.4,3.47, body extent -3.48,-3.25 3.48,3.25, height 1.68
DGS0010A_N [mm] "TSSOP, 10-Leads, Body 3x3mm, Pitch 0.5mm, IPC Medium Density"
  oval 1.35x0.3 smd: 1(-2.225,1) 2(-2.225,0.5) 3(-2.225,0) 4(-2.225,-0.5) 5(-2.225,-1) 6(2.225,-1) 7(2.225,-0.5) 8(2.225,0) 9(2.225,0.5) 10(2.225,1)
  silkscreen extent -2.75,-1.55 0.9,1.55, body extent -2.45,-1.5 2.45,1.5, height 0.96
DNK0008A [mm] "SON, 8-Leads, Body 5x6mm"
  rrect39% 0.86x0.51 smd paste-0.05 mask-0.05: 1(-2.82,1.905) 2(-2.82,0.635) 3(-2.82,-0.635) 4(-2.82,-1.905) 5(2.82,-1.905) 6(2.82,-0.635) 7(2.82,0.635) 8(2.82,1.905)
  rrect40% 0.25x0.555 on Top Solder: 9(-0.83,2.372) 9(-0.83,-2.372)
  rrect40% 0.25x0.555 on Top Paste: 9(-0.83,2.372) 9(-0.83,-2.372)
  rrect11% 0.95x1.13 on Top Paste: 9(-0.535,1.33) 9(-0.535,0) 9(-0.535,-1.33) 9(0.615,1.33) 9(0.615,0) 9(0.615,-1.33) 9(1.765,-1.33) 9(1.765,0) 9(1.765,1.33)
  rrect3% 3.58x4 on Top Solder: 9(0.75,0)
  rrect5% 4.34x5.4 smd paste-3 mask-3: 9(1.08,0)
  body extent -3.05,-2.55 3.05,2.55, height 1.06
FCC_disclaimer [mil]
Fiducial10-20#1 [mm]
  round 1 smd mask+0.5: 1(0,0)
  Top Layer keep-out circle w1.178: c0,0 r0.5
Fiducial10-20#2 [mm]
  round 1 smd far side mask+0.5: 1(0,0)
  Top Layer keep-out circle w1.178: c0,0 r0.5
Fuse_0463 [mm] "SMD, 2-Leads, Body 10.1x3.12mm"
  rrect3% 3.25x3.43 smd: 1(-4.675,0) 2(4.675,0)
  silkscreen extent -2.6,-1.5 2.6,1.5, body extent -5.05,-1.56 5.05,1.56, height 3.12
Harwin_D3082-05 [mm] "Shorting Plug, 10.16mm spacing, TH"
  round 1.8 hole 1.3: 1(-5.08,0) 2(5.08,0)
  silkscreen extent -3.9,-0.53 3.9,0.53, body extent -5.6,-0.52 5.61,0.52, height 6.63
IEC_HighVoltage_Small [mil]
  silkscreen extent -107,-88 107,97
IEC_HotSurface_Small [mil]
  silkscreen extent -107,-93 107,92
Keystone5000 [mil] "For Keystone 500x miniature loop terminals"
  round 80 hole 40: 1(0,0)
  silkscreen extent -52,-52 52,52, body extent -49,-49 49,49, height 182
Keystone5001 [mil] "For Keystone 500x miniature loop terminals"
  round 80 hole 40: 1(0,0)
  silkscreen extent -52,-52 52,52, body extent -49,-49 49,49, height 182
Keystone5002 [mil] "For Keystone 500x miniature loop terminals"
  round 80 hole 40: 1(0,0)
  silkscreen extent -52,-52 52,52, body extent -49,-49 49,49, height 182
Label_650x200 [mil] "Thermal Transfer Label"
  round 1 on Mech14: 0(0,0)
  silkscreen extent -325,-100 325,100, body extent -325,-100 325,100, height 1
LED_LTST-C171 [mm] "LITE-ON"
  rect 1.2x1.2 smd: 1(-1.05,0) 2(1.05,0)
  silkscreen extent -1.6,-1 2.2,1, body extent -1.05,-0.67 1.05,0.67, height 0.8
LRMA2512_under3 [mm] "Chip Resistor, Body 6.3x3.2mm"
  rect 3.1x4 smd: 1(-2.2,0) 2(2.2,0)
  silkscreen extent -0.4,-1.8 0.4,1.8, body extent -3.3,-1.7 3.3,1.7, height 0.9
Net-Tie_10mil [mil] "10mil net tie, no solder mask opening, no solder paste"
  rect 10x10 smd paste-5 mask-5: 1(-10,0) 2(10,0)
  Top Layer region: -6,5 6,5 6,-5 -6,-5
NGU0008B [mm] "SON, 8-Leads, Body 4x4mm, Pitch 0.8mm"
  rrect33% 0.6x0.3 smd: 1(-1.9,1.2) 2(-1.9,0.4) 3(-1.9,-0.4) 4(-1.9,-1.2) 5(1.9,-1.2) 6(1.9,-0.4) 7(1.9,0.4) 8(1.9,1.2)
  rrect5% 1.98x3 smd paste-1.5: 9(0,0)
  silkscreen extent -2.15,-2.15 2.15,2.15, body extent -2.05,-2.05 2.05,2.05, height 0.81
Phoenix_1902547 [mm] "TH, 2-Leads, Body 19.04x16mm, Pitch 9.52mm"
  rect 1.8x1.8 hole 1.3: 1(-4.76,3.1)
  round 1.8 hole 1.3: 2(4.76,3.1)
  silkscreen extent -10,-8 10.09,8, body extent -9.52,-8 10.09,8, height 22
PW0020A_N [mm] "TSOP, 20-Leads, Body 6.5x4.4mm, Pitch 0.65mm, IPC Medium Density"
  oval 1.4x0.45 smd: 1(-2.95,2.925) 2(-2.95,2.275) 3(-2.95,1.625) 4(-2.95,0.975) 5(-2.95,0.325) 6(-2.95,-0.325) 7(-2.95,-0.975) 8(-2.95,-1.625) 9(-2.95,-2.275) 10(-2.95,-2.925) 11(2.95,-2.925) 12(2.95,-2.275) 13(2.95,-1.625) 14(2.95,-0.975) 15(2.95,-0.325) 16(2.95,0.325) 17(2.95,0.975) 18(2.95,1.625) 19(2.95,2.275) 20(2.95,2.925)
  Top Overlay keep-out lines w0.2: -1.85,-3.3 1.85,-3.3
  silkscreen extent -3.5,-3.3 1.85,3.4, body extent -3.21,-3.25 3.21,3.25, height 1
RGE0024B-MFG [mm]
  rrect40% 0.6x0.25 smd paste+0 mask+0: 1(-1.9,1.25) 2(-1.9,0.75) 3(-1.9,0.25) 4(-1.9,-0.25) 5(-1.9,-0.75) 6(-1.9,-1.25) 13(1.9,-1.25) 14(1.9,-0.75) 15(1.9,-0.25) 16(1.9,0.25) 17(1.9,0.75) 18(1.9,1.25)
  rrect40% 0.25x0.6 smd paste+0 mask+0: 7(-1.25,-1.9) 8(-0.75,-1.9) 9(-0.25,-1.9) 10(0.25,-1.9) 11(0.75,-1.9) 12(1.25,-1.9) 19(1.25,1.9) 20(0.75,1.9) 21(0.25,1.9) 22(-0.25,1.9) 23(-0.75,1.9) 24(-1.25,1.9)
  rrect4% 2.45x2.45 smd paste-1000 mask+0: 25(0,0)
  silkscreen extent -2.92,-2.05 2.05,2.05, body extent -2.3,-2.3 2.3,2.3, height 0.25
SDR1006 [mm] "Bourns recommended land pattern"
  oval 3.6x10 smd: 1(-3.2,0) 2(3.2,0)
  rect 2x2 smd: 1(-2.4,4) 1(-2.4,-4) 2(2.4,4) 2(2.4,-4)
  silkscreen extent -5.4,-5.43 5.4,5.43, body extent -4.9,-4.9 4.86,4.88, height 5.8
SM_RADIAL_K16 [mm] "18 x 16.5mm:  Panasonic K16 (K18 from land pattern recommendation)"
  rect 7.5x2.5 smd: 1(-6.75,0) 2(6.75,0)
  silkscreen extent -9.6,-9.6 9.6,9.6, body extent -9.6,-9.6 9.6,9.6, height 17
SMA [mm] "Molded Diode, 2-Leads, Body 4.3x2.6mm, IPC Medium Density, based on OnSemi component dimensions and land pattern"
  rect 2x2 smd: 1(-2,0) 2(2,0)
  silkscreen extent -3.66,-1.57 2.79,1.57, body extent -2.6,-1.3 2.6,1.3, height 2.42
SNT-100-BK-G [mil] "Samtec STEP model"
  round 1 on Mech3: 0(0,0)
  body extent -100,-50 100,50, height 344
Sullins_xxC07SFAN [mm] "Header, 2.54 mm, 7x1, TH"
  rect 1.55x1.55 hole 1.016: 1(-7.62,0)
  round 1.55 hole 1.016: 2(-5.08,0) 3(-2.54,0) 4(0,0) 5(2.54,0) 6(5.08,0) 7(7.62,0)
  silkscreen extent -8.89,-1.28 8.89,1.7, body extent -8.89,-1.27 8.89,1.27, height 10.62
TI_Stacked_Overlay_Small [mil]
  silkscreen extent -418,-98 418,98
TP_SM_1MM [mm] "1mm Test Point, SMT"
  round 1 smd paste-0.5: 1(0,0)
TSW-104-07-G-S [mm] "Samtec 100mil, 1x4, 230 mil above insulator"
  rrect50% 1.65x1.65 hole 1.016: 1(-3.81,0)
  round 1.65 hole 1.016: 2(-1.27,0) 3(1.27,0) 4(3.81,0)
  body extent -5.08,-1.27 5.08,1.27, height 8.38
WEEE_Minimum [mil] "WEEElie bin"
  silkscreen extent -95,-172 99,104
WURTH_61300311121 [mm] "Header, 2.54mm, 3x1, TH"
  rrect50% 1.65x1.65 hole 1.15: 1(-2.54,0)
  round 1.65 hole 1.15: 2(0,0) 3(2.54,0)
  body extent -3.81,-1.27 3.81,1.27, height 8.54

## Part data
3.3V GVDD_EXT: library part CMP-0055137-1, "Test Point, Miniature, Red, TH", Color=Red, Manufacturer=Keystone, PartNumber=5000, Supplier Part Number 1=36-5000-ND
3.3V GVDD PVDD STATUS: library part CMP-0002830-3, "LED, Green, SMD", Color=green, Manufacturer=Lite-On, PartNumber=LTST-C171GKT, Value1=W, Value2=2.1V
C1 C4 C32: library part CMP-0083859-1, "CAP, CERM, 1 µF, 25 V,+/- 10%, X7R, 0805", Cap_Case=0805, Manufacturer="Samsung Electro-Mechanics", TempCo=X7R, Tolerance_%=10%, Value2=25V, ValueDisplayed=1µF
C2 C3: library part CMP-0011224-2, "CAP, AL, 330 uF, 100 V, +/- 20%, 0.153 ohm, AEC-Q200 Grade 2, SMD", Cap_Case=K16, Manufacturer=Panasonic, Supplier Part Number 1=PCE3505CT-ND, Tolerance_%=20%, Value1="0.153 ohm", Value2=100V, ValueDisplayed=330uF
C5 C6 C8: library part CMP-0009145-2, "CAP, CERM, 1 uF, 100 V, +/- 10%, X7R, AEC-Q200 Grade 1, 1210", Cap_Case=1210_220, Manufacturer=TDK, Supplier Part Number 1=445-5865-1-ND, TempCo=X7R, Tolerance_%=10%, Value1="0.004956 ohm", Value2=100V, ValueDisplayed=1uF
C7: library part CMP-0006848-4, "CAP, CERM, 0.01 uF, 100 V, +/- 5%, X7R, 0603", Cap_Case=0603, Manufacturer=Kemet, Supplier Part Number 1=399-3190-1-ND, TempCo=X7R, Tolerance_%=5%, Value1=Unknown, Value2=100V, ValueDisplayed=0.01uF
C9: library part CMP-0007085-4, "CAP, CERM, 2200 pF, 100 V, +/- 10%, X7R, AEC-Q200 Grade 1, 0603", Cap_Case=0603, Manufacturer=TDK, Supplier Part Number 1=445-5808-1-ND, TempCo=X7R, Tolerance_%=10%, Value1="0.923948 ohm", Value2=100V, ValueDisplayed=2200pF
C10: library part CMP-0007275-4, "CAP, CERM, 56 pF, 100 V, +/- 5%, C0G/NP0, 0603", Cap_Case=0603, Manufacturer=MuRata, Supplier Part Number 1=490-1345-1-ND, TempCo=C0G/NP0, Tolerance_%=5%, Value1=Unknown, Value2=100V, ValueDisplayed=56pF
C11: library part CMP-0008656-2, "CAP, CERM, 47 uF, 25 V, +/- 20%, X5R, 1206_190", Cap_Case=1206, Manufacturer=TDK, Supplier Part Number 1=445-8047-1-ND, TempCo=X5R, Tolerance_%=20%, Value1=Unknown, Value2=25V, ValueDisplayed=47uF
C12: library part CMP-0079201-1, "CAP, CERM, 10 µF, 50 V,+/- 10%, X7R, 1210", Cap_Case=1210, Manufacturer="Samsung Electro-Mechanics", Supplier Part Number 1=1276-3388-1-ND, TempCo=X7R, Tolerance_%=10%, Value1="0.005 ohm", Value2=50V, ValueDisplayed=10µF
C13: library part CMP-0007575-2, "CAP, CERM, 0.33 uF, 25 V, +/- 10%, X5R, 0805", Cap_Case=0805, Manufacturer=AVX, Supplier Part Number 1=478-1406-1-ND, TempCo=X5R, Tolerance_%=10%, Value1="0.02 ohm", Value2=25V, ValueDisplayed=0.33uF
C14: library part CMP-0006857-4, "CAP, CERM, 0.1 uF, 16 V, +/- 5%, X7R, 0603", Cap_Case=0603, Manufacturer=Kemet, Supplier Part Number 1=399-1097-1-ND, TempCo=X7R, Tolerance_%=5%, Value1=Unknown, Value2=16V, ValueDisplayed=0.1uF
C15: library part CMP-0006268-2, "CAP, CERM, 4.7 uF, 10 V, +/- 10%, X5R, 0402", Cap_Case=0402_065, Manufacturer=TDK, Supplier Part Number 1=445-13820-1-ND, TempCo=X5R, Tolerance_%=10%, Value1="0.003417 ohm", Value2=10V, ValueDisplayed=4.7uF
C16: library part CMP-0006862-5, "CAP, CERM, 0.1 uF, 10 V, +/- 10%, X7R, 0603", Cap_Case=0603, Manufacturer=Kemet, Supplier Part Number 1=399-1095-1-ND, TempCo=X7R, Tolerance_%=10%, Value1=Unknown, Value2=10V, ValueDisplayed=0.1uF
C17: library part CMP-0006844-4, "CAP, CERM, 1000 pF, 50 V, +/- 5%, X7R, AEC-Q200 Grade 1, 0603", Cap_Case=0603, Manufacturer=Kemet, Supplier Part Number 1=399-12989-1-ND, TempCo=X7R, Tolerance_%=5%, Value1=Unknown, Value2=50V, ValueDisplayed=1000pF
C18 C19 C24 C25: library part CMP-0006737-4, "CAP, CERM, 2200 pF, 100 V, +/- 10%, X7R, 0603", Cap_Case=0603, Manufacturer=AVX, Supplier Part Number 1=478-1201-1-ND, TempCo=X7R, Tolerance_%=10%, Value1="0.192 ohm", Value2=100V, ValueDisplayed=2200pF
C20 C21 C22 C23: library part CMP-0007475-4, "CAP, CERM, 2200 pF, 100 V, +/- 10%, X7R, 0603", Cap_Case=0603, Manufacturer=MuRata, Supplier Part Number 1=490-1478-1-ND, TempCo=X7R, Tolerance_%=10%, Value1=Unknown, Value2=100V, ValueDisplayed=2200pF
C26: library part CMP-0079150-1, "CAP, CERM, 0.1 µF, 10 V,+/- 10%, X7R, AEC-Q200 Grade 1, 0402", Cap_Case=0402, Manufacturer=Kemet, Supplier Part Number 1=399-15984-1-ND, TempCo=X7R, Tolerance_%=10%, Value2=10V, ValueDisplayed=0.1µF
C27 C28: library part CMP-0006834-5, "CAP, CERM, 470 pF, 50 V, +/- 10%, X7R, 0603", Cap_Case=0603, Manufacturer="Wurth Elektronik", Supplier Part Number 1=710-885012206081, TempCo=X7R, Tolerance_%=10%, Value1=Unknown, Value2=50V, ValueDisplayed=470pF
C29 C30 C31: library part CMP-0006723-4, "CAP, CERM, 1000 pF, 100 V, +/- 5%, X7R, 0603", Cap_Case=0603, Manufacturer=AVX, Supplier Part Number 1=478-3698-1-ND, TempCo=X7R, Tolerance_%=5%, Value1="0.276 ohm", Value2=100V, ValueDisplayed=1000pF
D1 D2 D3 D7: library part CMP-0005527-4, "Diode, Zener, 16 V, 1 W, SMA", Manufacturer="Diodes Inc.", Power_W=1W
D4 D5 D6 D8: library part CMP-0076923-3, "Diode, Schottky, 40 V, 2 A, SMA", Manufacturer=Vishay-Semiconductor, Value1=2A, Value2=0.49V
F1: library part CMP-0077200-3, "Fuse, 30 A, 250 VAC, 100 VDC, SMD", Irating_A=30A, Manufacturer=Littelfuse, PartNumber=0463030.ER, Supplier Part Number 1=F6439CT-ND
FID1 FID2 FID3 FID4 FID5 FID6: library part CMP-0077181-1, "Fiducial mark.  There is nothing to buy or mount.", Manufacturer=N/A
GHA1 GHB1 GLA1 GLB1 SHA1 SHB1: library part CMP-0055139-1, "Test Point, Miniature, White, TH", Color=White, Manufacturer=Keystone, Supplier Part Number 1=36-5002-ND
GND: library part CMP-0055138-1, "Test Point, Miniature, Black, TH", Color=Black, Manufacturer=Keystone, Supplier Part Number 1=36-5001-ND
GND: library part CMP-0075110-1, "1mm Uninsulated Shorting Plug, 10.16mm spacing, TH", Manufacturer=Harwin, Supplier Part Number 1=952-1873-ND
H1 H2 H3 H4: library part CMP-0003621-1, "Bumpon, Cylindrical, 0.312 X 0.200, Black", Manufacturer=3M, Supplier Part Number 1=SJ5746-0-ND
J1 J7 J8: library part CMP-0055527-1, "Terminal Block, 9.52mm, 2x1, R/A, TH", Color=Green, Current_A=32A, Manufacturer="Phoenix Contact", PartNumber=1902547, Supplier Part Number 1=277-5951-ND, Voltage_V=1kV
J2 J6: library part CMP-0054796-2, "Header, 2.54 mm, 3x1, Gold, TH", Color=Black, Manufacturer="Wurth Elektronik", PartNumber=61300311121, Supplier Part Number 1=732-5316-ND
J3: library part CMP-0055060-1, "SOCKET .050\" GRID SIP 4 POS R/A, TH", Manufacturer=Mill-Max, Supplier Part Number 1=ED90474-ND
J4: library part CMP-0075409-2, "Header, 100mil, 4x1, Gold, TH", Color=Black, Current_A=6.3A, Manufacturer=Samtec, Supplier Part Number 1=SAM1029-04-ND, Voltage_V=550V
J5: library part CMP-0054600-1, "Header, 2.54 mm, Gold, 7x1, TH", Color=Black, Current_A=3A, Manufacturer="Sullins Connector Solutions", Supplier Part Number 1=S1211E-07-ND, Voltage_V=1.8kV
L1: library part CMP-0057541-2, "Inductor, Drum Core, Ferrite, 68 uH, 1.1 A, 0.22 ohm, SMD", Manufacturer=Bourns, Supplier Part Number 1=SDR1006-680KLCT-ND, Value1="0.22 ohm", Value2=1.1A, ValueDisplayed=68uH
LBL1: library part CMP-0003625-1, "Thermal Transfer Printable Labels, 0.650\" W x 0.200\" H - 10,000 per roll", Manufacturer=Brady, Supplier Part Number 1=97C5133
Logo1: library part CMP-0074844-1
Logo2: library part CMP-0074838-1, "Texas Instrument Corporate Signature"
Logo3: library part CMP-0074847-1, "FCC_disclaimer"
Logo4: library part CMP-0074769-1
LOGO5 LOGO6: library part CMP-0074837-1, "IEC 61010-1 Hot Surface Warning"
LOGO7 LOGO8: library part CMP-0074835-1, "IEC 61010-1 High Voltage Warning"
NT1 NT2 NT3 NT4: library part CMP-0078142-4, "Single point connection between nets.", Manufacturer=N/A
PVDD: library part CMP-0055137-1, "Test Point, Miniature, Red, TH", Color=Red, Manufacturer=Keystone, Supplier Part Number 1=36-5000-ND
Q1 Q2 Q3 Q4: library part CMP-0000958-3, "MOSFET, N-CH, 100 V, 17 A, DNK0008A (VSON-CLIP-8)", Alternate Manufacturer=None, Manufacturer="Texas Instruments", Supplier Part Number 1=296-37478-6-ND, Value2="48 nC"
R1 R19 R34 R45: library part CMP-0020617-3, "RES, 10, 5%, 0.125 W, AEC-Q200 Grade 0, 0805", Manufacturer=Panasonic, Power_W=125mW, Supplier Part Number 1=P10ACT-ND, TempCo="200 ppm/C", Tolerance_%=5%, Value2=0.125W, Value_Code=10R0, ValueDisplayed=10
R2 R17 R25 R31: library part CMP-0020521-3, "RES, 2.7, 5%, 0.125 W, AEC-Q200 Grade 0, 0805", Manufacturer=Vishay-Dale, Power_W=125mW, Supplier Part Number 1=541-2.7ACT-ND, TempCo="200 ppm/C", Tolerance_%=5%, Value2=0.125W, Value_Code=2R70, ValueDisplayed=2.7
R3 R11 R12 R13 R16: library part CMP-0025697-4, "RES, 0, 5%, 0.1 W, AEC-Q200 Grade 0, 0603", Manufacturer=Vishay-Dale, Power_W=100mW, Supplier Part Number 1=541-0.0GCT-ND, TempCo="200 ppm/C", Tolerance_%=5%, Value2=0.1W, Value_Code=0000, ValueDisplayed=0
R4: library part CMP-0025736-4, "RES, 1.0 M, 5%, 0.1 W, AEC-Q200 Grade 0, 0603", Manufacturer=Vishay-Dale, Power_W=100mW, Supplier Part Number 1=541-1.0MGCT-ND, TempCo="200 ppm/C", Tolerance_%=5%, Value2=0.1W, Value_Code=1M00, ValueDisplayed=1.0M
R5: library part CMP-0023236-4, "RES, 681 k, 1%, 0.1 W, 0603", Manufacturer=Yageo, Power_W=100mW, Supplier Part Number 1=311-681KHRCT-ND, TempCo="100 ppm/C", Tolerance_%=1%, Value2=0.1W, Value_Code=681k
R6: library part CMP-0023120-4, "RES, 453 k, 1%, 0.1 W, 0603", Manufacturer=Yageo, Power_W=100mW, Supplier Part Number 1=311-453KHRCT-ND, TempCo="100 ppm/C", Tolerance_%=1%, Value2=0.1W, Value_Code=453k
R7: library part CMP-0025784-4, "RES, 330 k, 5%, 0.1 W, AEC-Q200 Grade 0, 0603", Manufacturer=Vishay-Dale, Power_W=100mW, Supplier Part Number 1=541-330KGCT-ND, TempCo="200 ppm/C", Tolerance_%=5%, Value2=0.1W, Value_Code=330k
R8: library part CMP-0025950-3, "RES, 100 k, 1%, 0.063 W, AEC-Q200 Grade 0, 0402", Manufacturer=Vishay-Dale, Power_W=63mW, Supplier Part Number 1=541-100KLCT-ND, TempCo="100 ppm/C", Tolerance_%=1%, Value2=0.063W, Value_Code=100k
R9: library part CMP-0023142-5, "RES, 49.9 k, 1%, 0.1 W, 0603", Manufacturer=Yageo, Power_W=100mW, Supplier Part Number 1=311-49.9KHRCT-ND, TempCo="100 ppm/C", Tolerance_%=1%, Value2=0.1W, Value_Code=49k9, ValueDisplayed=49.9k
R10: library part CMP-0020443-3, "RES, 0, 5%, 0.333 W, AEC-Q200 Grade 0, 0805", Manufacturer=Vishay-Dale, Power_W=333mW, Supplier Part Number 1=541-0.0TBCT-ND, TempCo="200 ppm/C", Tolerance_%=5%, Value2=0.333W, Value_Code=0000, ValueDisplayed=0
R14 R20: library part CMP-0025785-4, "RES, 330, 5%, 0.1 W, AEC-Q200 Grade 0, 0603", Manufacturer=Vishay-Dale, Power_W=100mW, Supplier Part Number 1=541-330GCT-ND, TempCo="200 ppm/C", Tolerance_%=5%, Value2=0.1W, Value_Code=330R, ValueDisplayed=330
R15: library part CMP-0025814-4, "RES, 47 k, 5%, 0.1 W, AEC-Q200 Grade 0, 0603", Manufacturer=Vishay-Dale, Power_W=100mW, Supplier Part Number 1=541-47KGCT-ND, TempCo="200 ppm/C", Tolerance_%=5%, Value2=0.1W, Value_Code=47k0, ValueDisplayed=47k
R18 R21 R24 R29 R37 R38: library part CMP-0021990-4, "RES, 100 k, 1%, 0.1 W, AEC-Q200 Grade 0, 0603", Manufacturer=Vishay-Dale, Power_W=100mW, Supplier Part Number 1=541-100KHCT-ND, TempCo="100 ppm/C", Tolerance_%=1%, Value2=0.1W, Value_Code=100k
R22 R27 R46 R47: library part CMP-0020643-3, "RES, 15, 5%, 0.125 W, AEC-Q200 Grade 0, 0805", Manufacturer=Panasonic, Power_W=125mW, Supplier Part Number 1=P15ACT-ND, TempCo="200 ppm/C", Tolerance_%=5%, Value2=0.125W, Value_Code=15R0, ValueDisplayed=15
R23 R28 R35 R36 R39 R40 R41 R42 R43 R44 R48 R49 R50: library part CMP-0081973-1, "RES, 0, 0%, 0.25 W, AEC-Q200 Grade 0, 0603", Manufacturer=Vishay-Dale, Power_W=250mW, Supplier Part Number 1=541-2779-1-ND, Tolerance_%=0%, Value2=0.25W, Value_Code=0
R26 R33: library part CMP-0015826-2, "RES, 0.002, 1%, 3 W, AEC-Q200 Grade 0, 2512", Manufacturer="TT Electronics/IRC", Power_W=3W, Supplier Part Number 1=985-1557-1-ND, TempCo="50 ppm/C", Tolerance_%=1%, Value_Code=2L000, ValueDisplayed=0.002
R30 R32: library part CMP-0022458-4, "RES, 4.99 k, 1%, 0.1 W, AEC-Q200 Grade 0, 0603", Manufacturer=Vishay-Dale, Power_W=100mW, Supplier Part Number 1=541-4.99KHCT-ND, TempCo="100 ppm/C", Tolerance_%=1%, Value2=0.1W, Value_Code=4k99, ValueDisplayed=4.99k
RP1 RP2 RP3: library part CMP-0001777-2, "Trimming Potentiometer, 50K, 0.5W, TH", Manufacturer=Bourns, Supplier Part Number 1=3352T-503LF-ND
SH-J1 SH-J2: library part CMP-0003623-3, "Shunt, 100mil, Gold plated, Black", Alternate Manufacturer=3M, Alternate PartNumber=969102-0000-DA, Manufacturer=Samtec, Supplier Part Number 1=SAM8858-ND
TP1 TP2: library part CMP-0003825-1, "1mm Test Point, SMT", Manufacturer=Any
U1: library part CMP-0091750-2, "100-V Brushed DC Gate Driver", Manufacturer="Texas Instruments", Max Supply Voltage=20V, Min Supply Voltage=5V, Nominal Supply Current=825uA, Operating Temperature Range="-40°C to +150°C", Switching Frequency=200kHz
U2: library part CMP-0066087-1, "7.5-100V Wide Vin, 600mA Constant On-Time Synchronous Buck Regulator, NGU0008B (WSON-8)", Alternate Manufacturer="Texas Instruments", Alternate PartNumber=LM5017SD/NOPB
U3: library part CMP-0080825-1, "500-mA, 25-V, Linear Voltage Regulators, DCY0004A (SOT-223-4)", Alternate Manufacturer="Texas Instruments", Alternate PartNumber=UA78M33CDCY
U4: library part CMP-0039637-1, "16 MHz Mixed Signal Microcontroller with 16 KB Flash, 512 B SRAM and 24 GPIOs, -40 to 85 degC, 20-pin SOP (PW), Green (RoHS & no Sb/Br)", Frequency(MHz)=16, Manufacturer="Texas Instruments", Temp Sensor=Yes
U5: library part CMP-0013323-2, "Bidirectional, Low- and High-Side Measurement, Multichannel, Voltage Output, Current-Sense Amplifiers, DGS0010A (VSSOP-10)", Alternate Manufacturer="Texas Instruments"
U6: library part CMP-0081556-1, "Low-Power, Rail-to-Rail In and Out, 1-MHz Operational Amplifier, DCK0005A (SOT-SC70-5)", Alternate Manufacturer="Texas Instruments", Alternate PartNumber=TLV9001IDCKT
ZZ1: library part CMP-0003616-3
ZZ2: library part CMP-0077236-1
ZZ3: library part CMP-0077237-1
ZZ4: library part CMP-0077238-1

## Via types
v1: diameter 25/25/25/25 (per signal layer), hole 12, Top Layer to Bottom Layer, tented both sides, 566 vias
v2: diameter 19.68, hole 7.87, Top Layer to Bottom Layer, 9 vias
v3: diameter 26, hole 12, Top Layer to Bottom Layer, tented both sides, 4 vias

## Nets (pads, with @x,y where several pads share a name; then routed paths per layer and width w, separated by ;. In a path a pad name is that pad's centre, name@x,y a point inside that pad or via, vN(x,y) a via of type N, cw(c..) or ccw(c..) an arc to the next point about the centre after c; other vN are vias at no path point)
3.3V: 3.3V.1 C15.1 C16.1 C26.1 R13.2 R15.2 R16.2 R37.2 RP1.3 RP2.3 RP3.3 U4.1 U5.10 U6.5 | length 5397.5
  Top Layer w10: v1(2042.81,414.23) C26.1@2042.81,381.66 2059.15,381.66 2078.25,400.75 U5.10@2112.01,400.75
  Top Layer w12: C16.1@468.5,873.03 U4.1@602.36,873.03 599.41,875.98 C15.1@521.65,875.98 ; 3.3V.1@482.89,1764.59 v1(537.98,1764.59) ; U6.5@1750.79,397.35 1750.32,396.87 v1(1750.32,350.36) 1910.64,350.36 R37.2@1919.29,341.72
  Top Layer w20: v1(397.07,875.98) 466.54,875.98 C16.1@468.5,877.95 519.68,877.95 C15.1@521.65,875.98 ; v1(633.86,374.02) R16.2@712.4,374.02 R15.2@813.88,374.02 ; 3.3V.1@856.3,1564.22 949.56,1564.22 R13.2@980.64,1533.14
  Signal Layer 2 w20: v1(397.07,875.98) 177.17,875.98 ; 3.3V.1@856.3,1564.22 655.93,1764.59 v1(537.98,1764.59) 306.89,1533.49 RP1.3@110.65,1533.49 167.32,1476.82 167.32,1074.41 RP2.3@108.27,1015.35 177.17,946.46 177.17,875.98 ; v1(2042.81,414.23) 1978.94,350.36 v1(1750.32,350.36) 1631.19,350.36 1583.1,302.27 705.6,302.27 v1(633.86,374.02) 220.32,374.02 RP3.3@108.3,486.04 177.17,554.9 177.17,875.98
3.3V_SBW: J3.4 J4.4 R16.1 | length 387.7
  Top Layer w12: R16.1@712.4,314.96 835.83,191.54 J3.4@835.83,137.8
  Signal Layer 2 w12: J4.4@681.75,150.63 822.99,150.63 J3.4@835.83,137.8
GHA: R19.1 R27.1 U1.19 | length 1451
  Top Layer w10: U1.19@2085.44,1155.03 2095.87,1155.03 v1(2116.14,1175.3)
  Top Layer w20: v3(2676.9,1646.31) 2675.17,1648.04 2695.39,1668.26 R27.1@3003.97,1668.26
  Bottom Layer w12: v1(2116.14,1175.3) 2116.14,1448.08 2198.03,1529.97 2674.06,1529.97 2738.94,1594.85 R19.1@2738.94,1648.04
  Bottom Layer w20: v3(2676.9,1646.31) 2737.21,1646.31 R19.1@2738.94,1648.04
GHB: R1.1 R22.1 U1.16 | length 1205.3
  Top Layer w10: U1.16@2111.03,1090.07 2135.83,1090.07 2145.67,1080.23 v1(2169.24,1080.23)
  Top Layer w20: v3(2658,843.03) 2658,846.57 2682.24,870.82 R22.1@3044.88,870.82
  Bottom Layer w12: v1(2169.24,1080.23) 2333.64,1080.23 2345.22,1068.65 2614.4,1068.65 2658,1025.04 v3(2658,843.03)
  Bottom Layer w20: v3(2658,843.03) 2706.22,843.03 R1.1@2706.69,843.5
GLA: R34.1 R47.1 U1.11 | length 502
  Top Layer w10: v1(2065.75,954.72) U1.11@2065.75,1005.42
  Bottom Layer w20: v1(2065.75,954.72) 2183.12,837.35 R47.1@2381.89,837.35 R34.1@2381.89,750.78
GLB: R45.1 R46.1 U1.10 | length 830
  Top Layer w10: v1(2026.38,967.82) 2046.07,987.51 U1.10@2046.07,1005.42
  Bottom Layer w20: v1(2026.38,967.82) 2026.38,867.32 2381.89,511.81 R45.1@2381.89,421.47 R46.1@2381.89,330.82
